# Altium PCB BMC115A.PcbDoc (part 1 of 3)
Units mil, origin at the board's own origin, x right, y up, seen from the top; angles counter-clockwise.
Board outline 5500 x 3200 mil, 4 copper layers (Top Layer, Signal Layer 1, Signal Layer 2, Bottom Layer), stack 61.6 mil thick; 199 components, 81 nets, 456 pads, 1349 vias.
Unrouted connection lines stored in the file: 741.
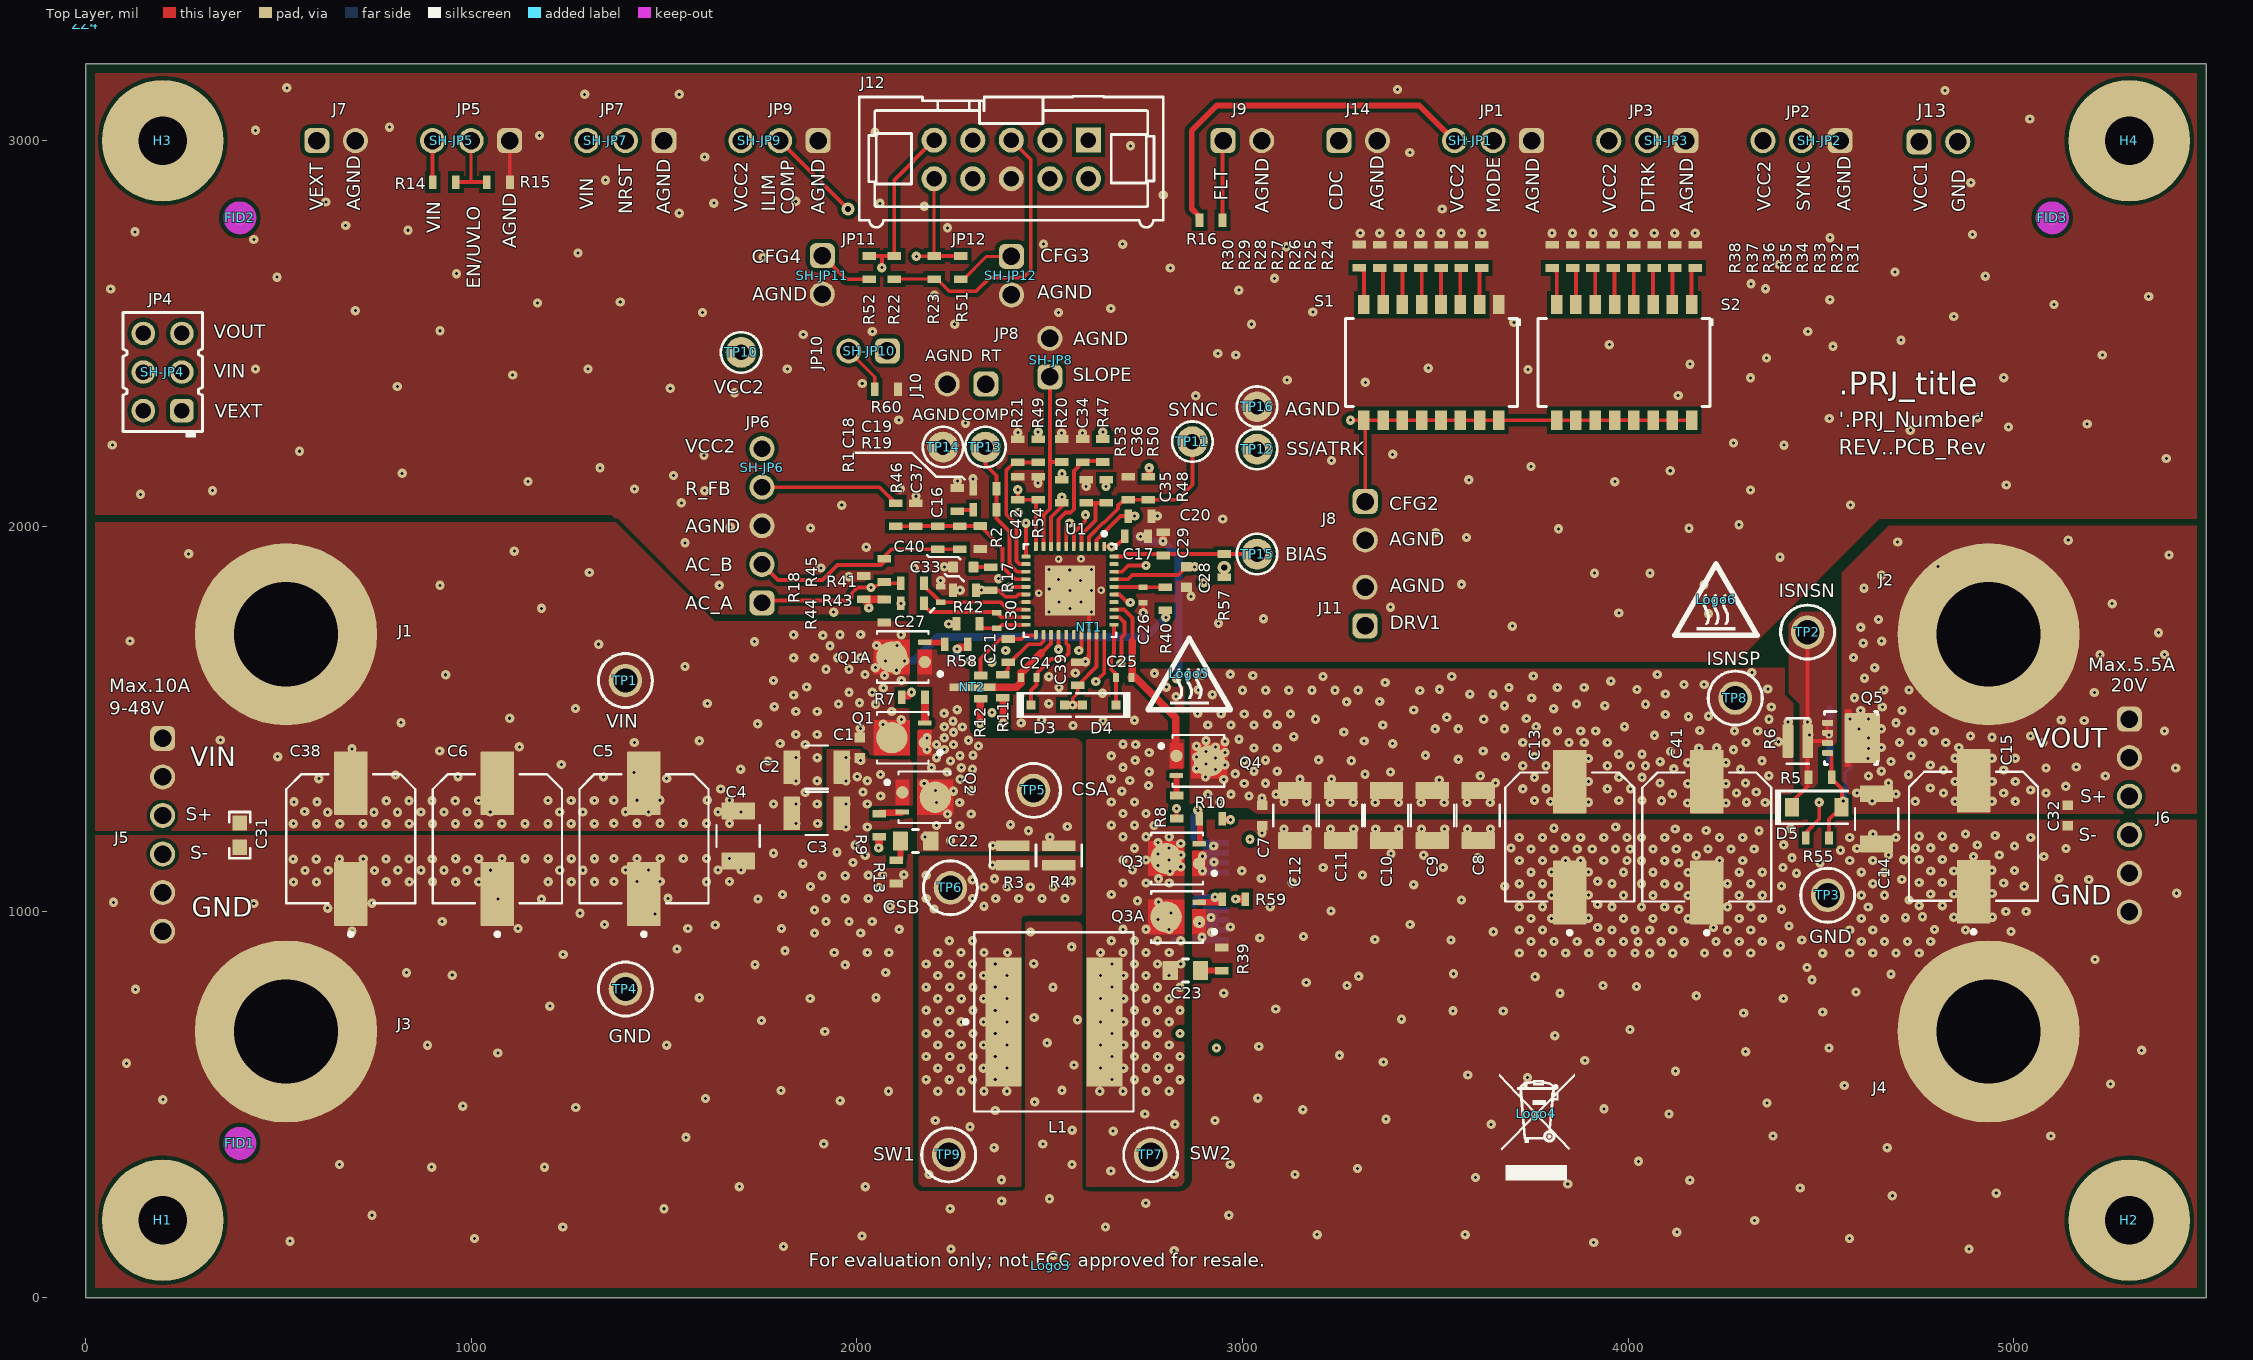
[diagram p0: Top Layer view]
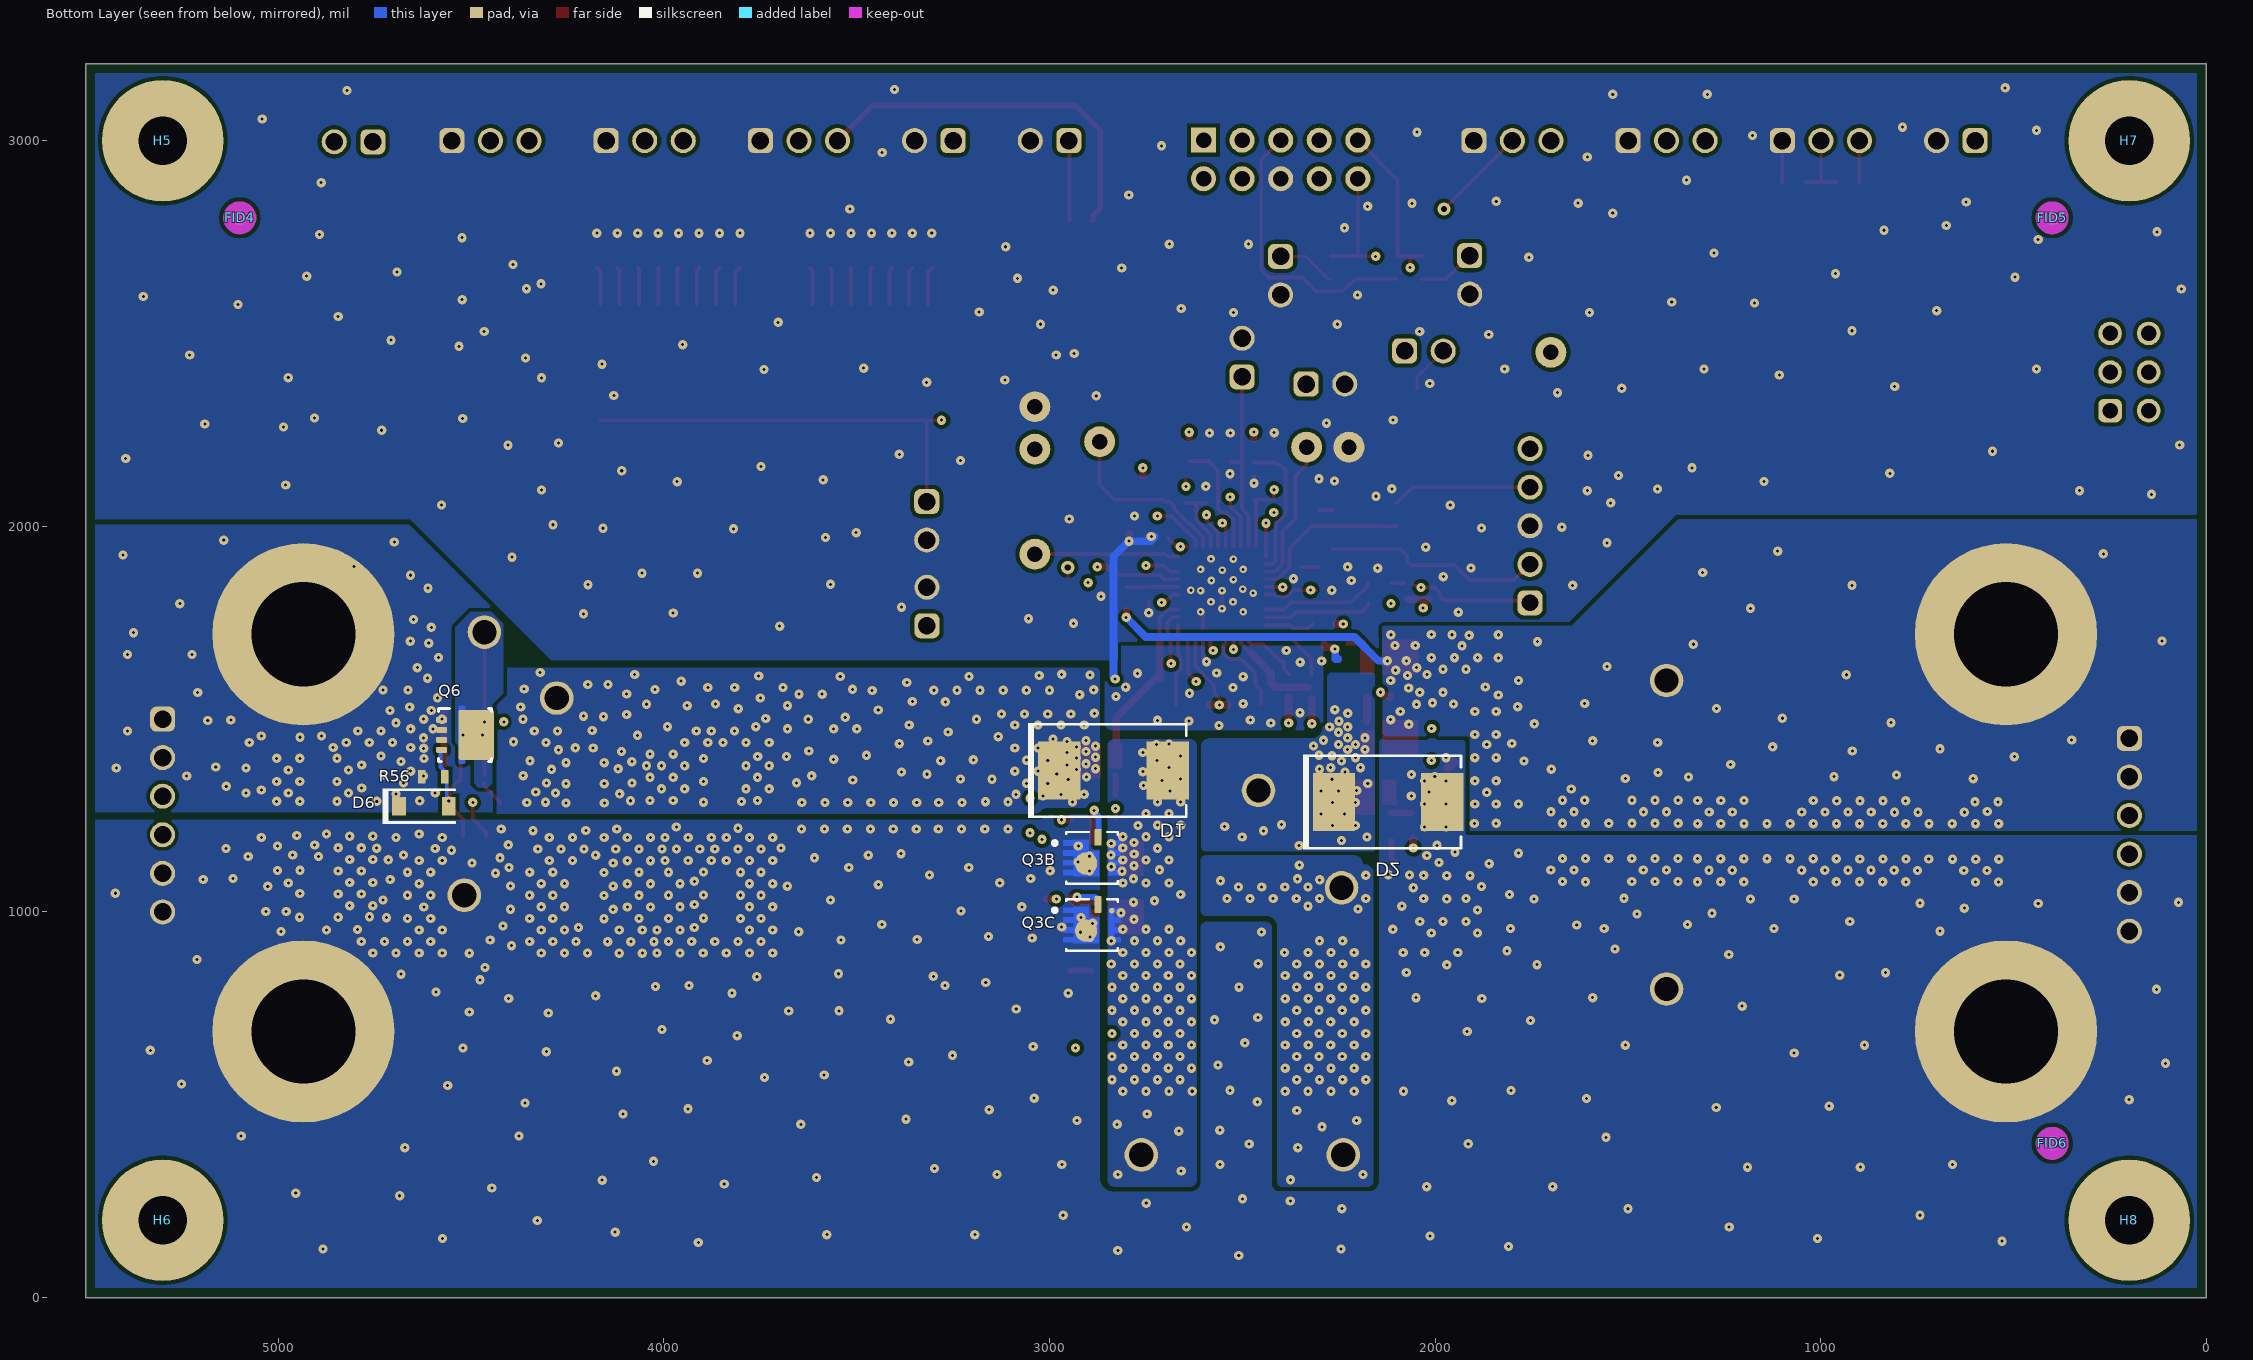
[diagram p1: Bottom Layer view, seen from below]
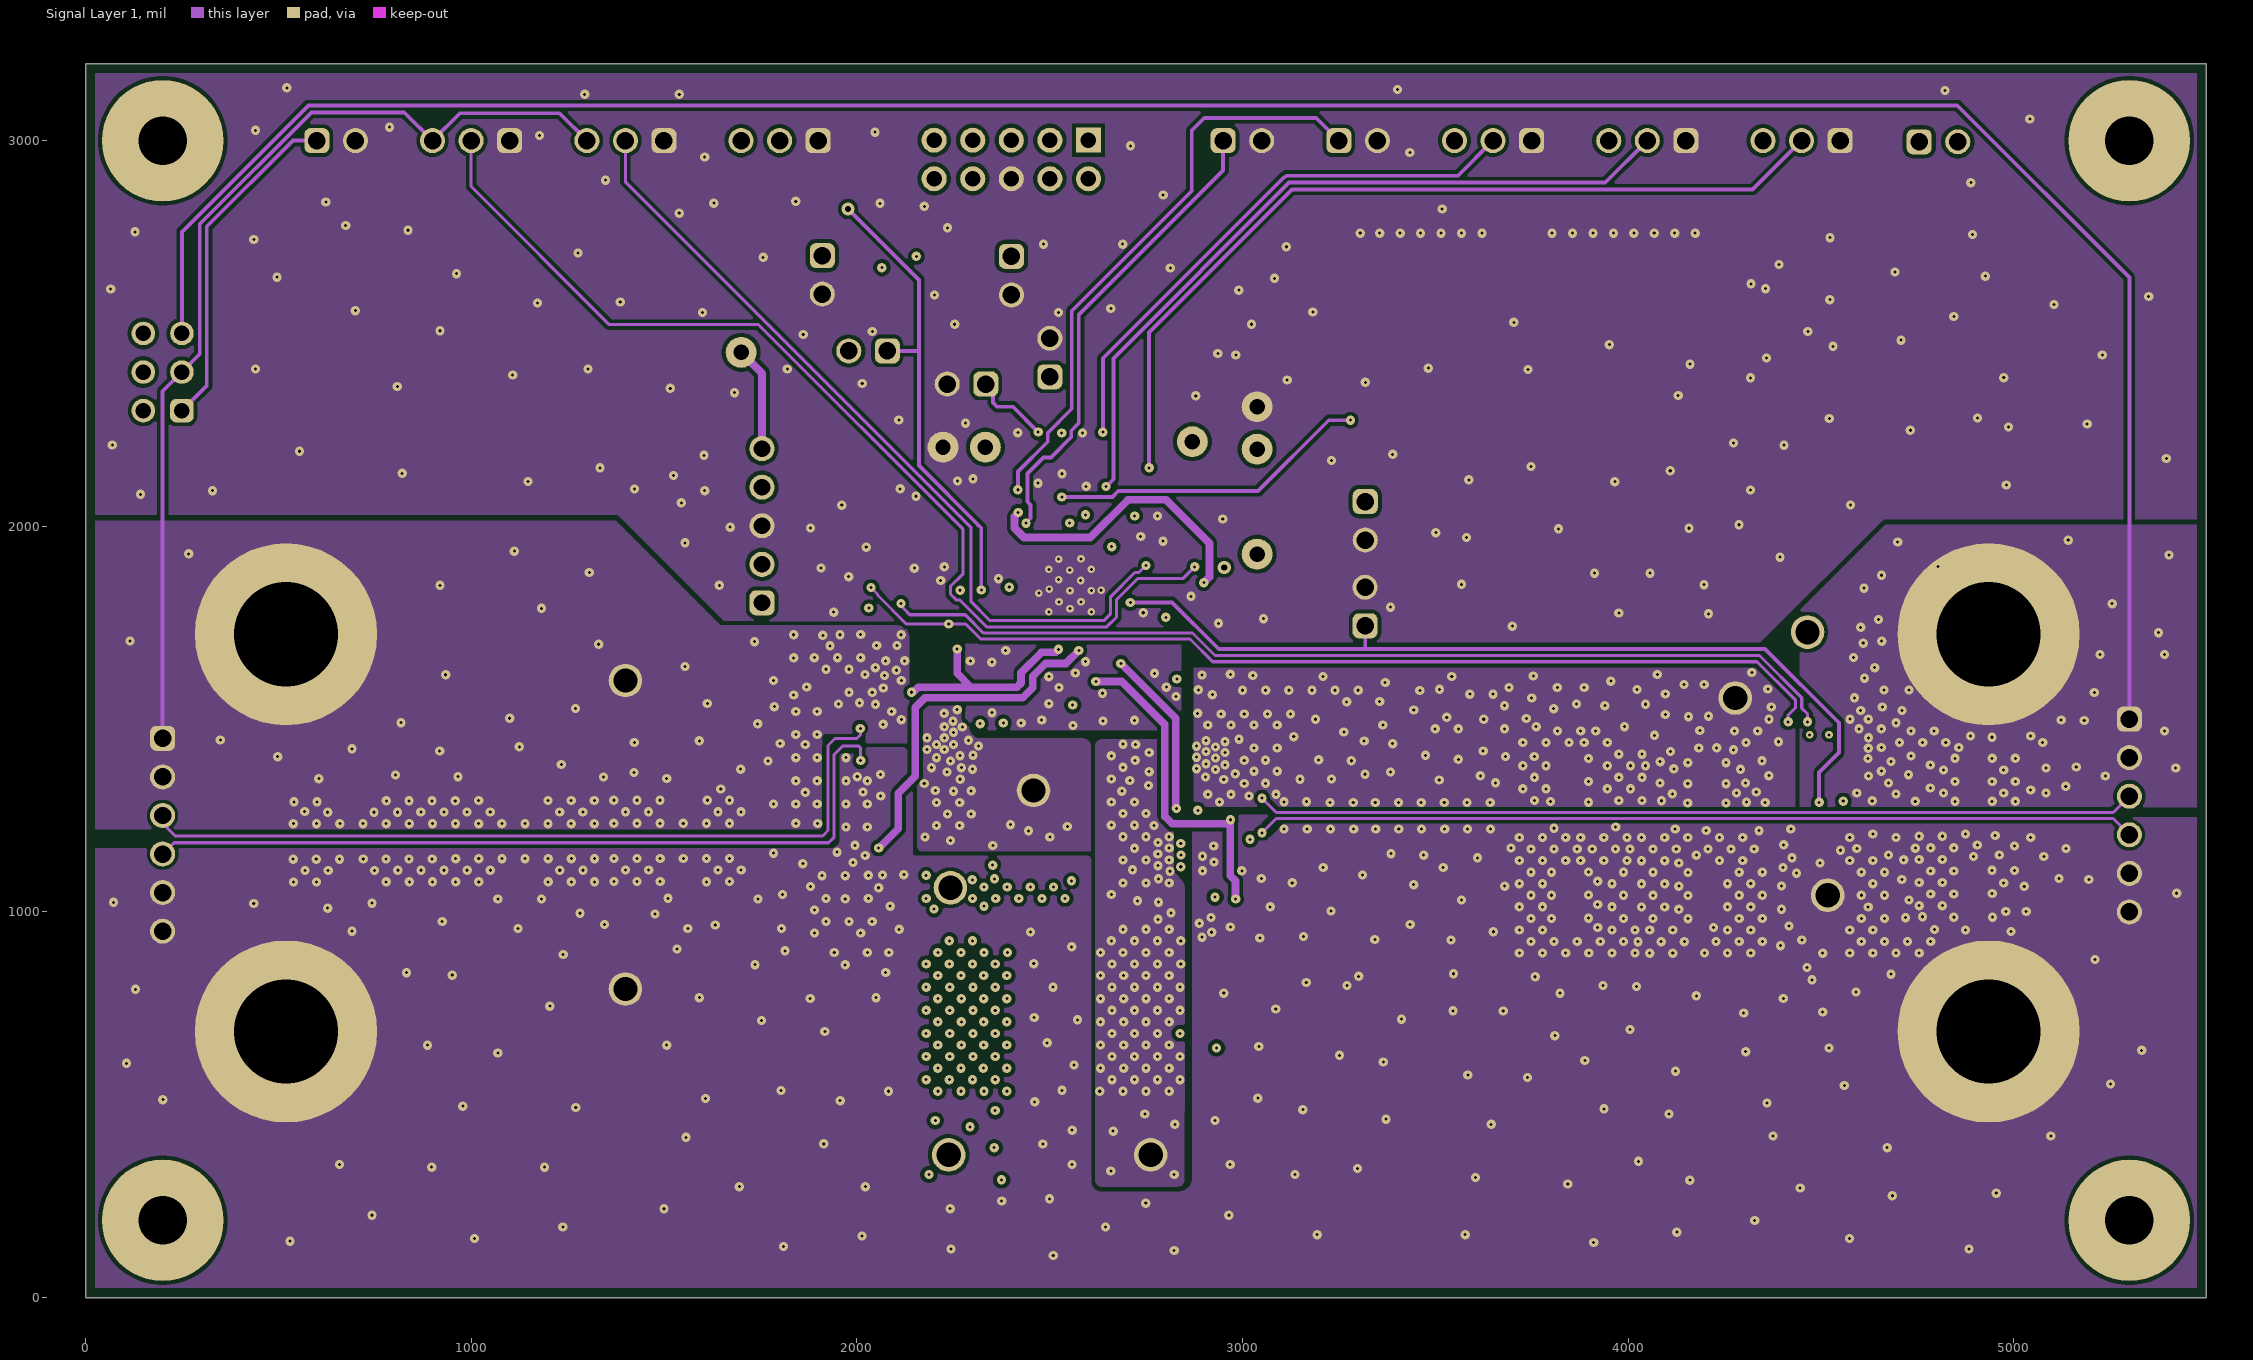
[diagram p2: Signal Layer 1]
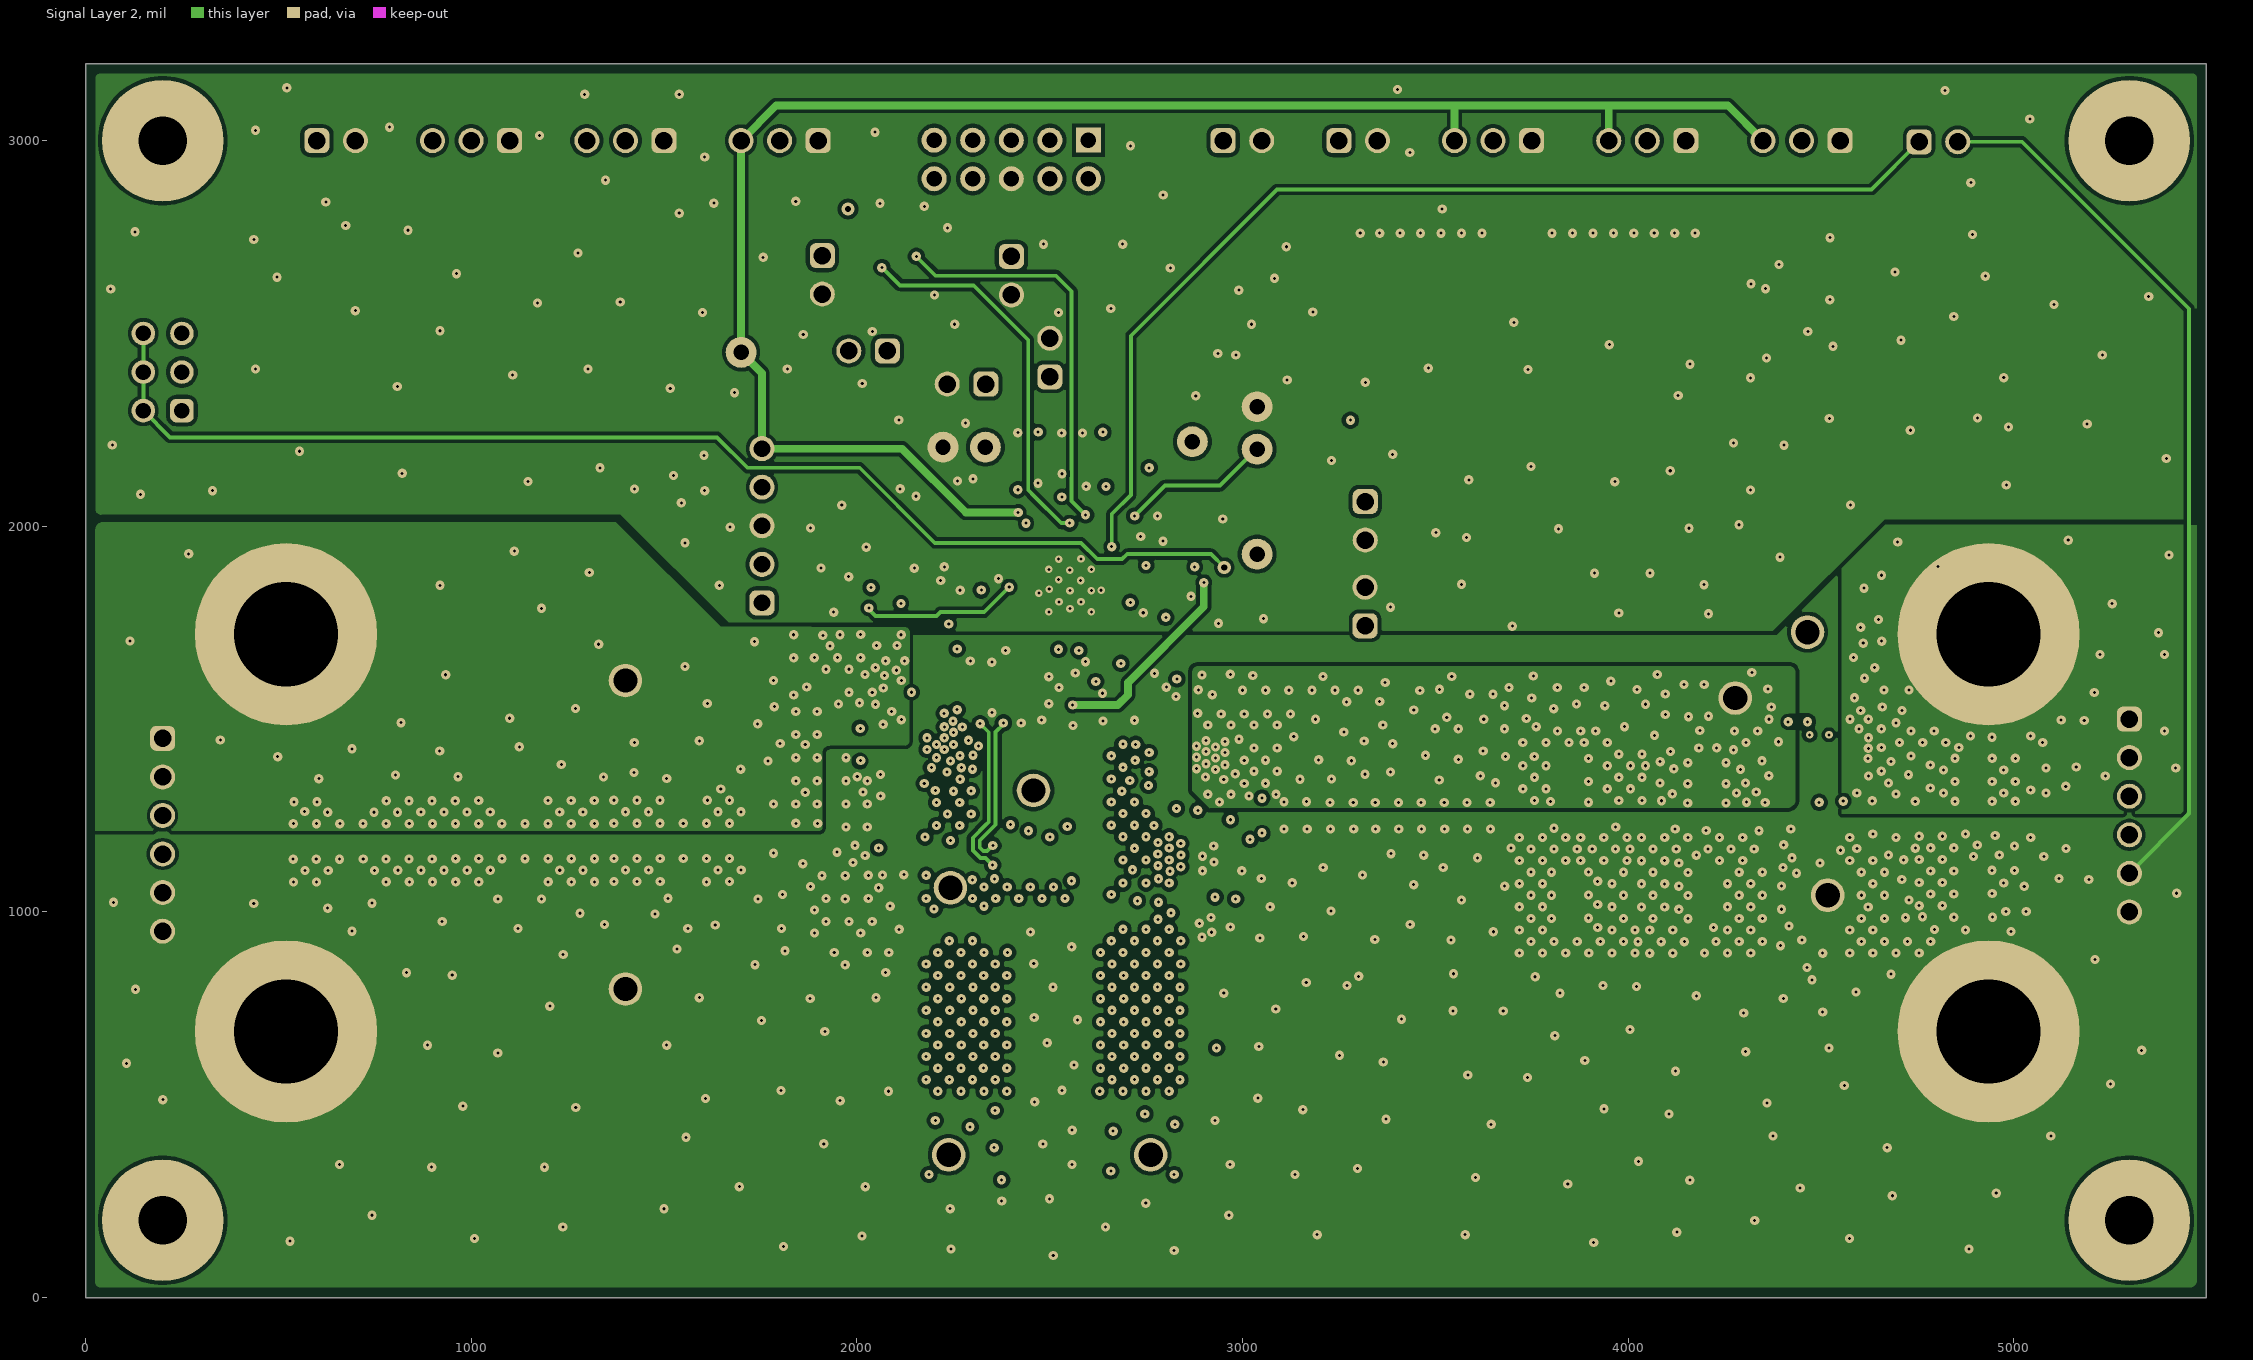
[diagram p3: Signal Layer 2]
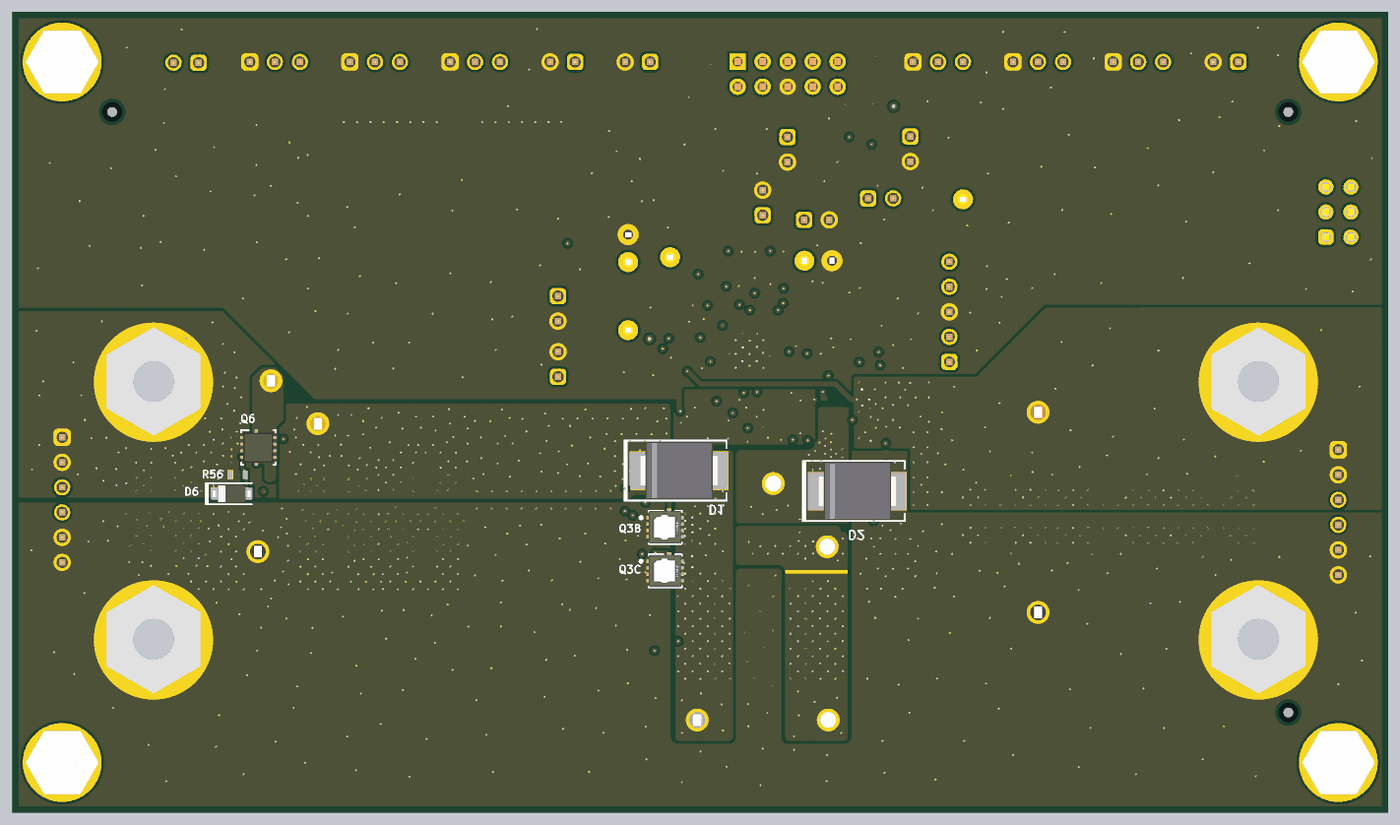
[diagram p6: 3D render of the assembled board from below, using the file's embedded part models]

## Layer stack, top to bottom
Top Solder: solder mask 0.4, Solder Resist, Dk 3.5
Top Layer: signal copper 2.8
Dielectric 1: prepreg 8, FR-4 High Tg, Dk 4.2
Signal Layer 1: signal copper 1.4
Dielectric 2: core 37.2, FR-4 High Tg, Dk 4.2
Signal Layer 2: signal copper 1.4
Dielectric 3: prepreg 8, FR-4 High Tg, Dk 4.2
Bottom Layer: signal copper 2.8
Bottom Solder: solder mask 0.4, Solder Resist, Dk 3.5

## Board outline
5500,0 5500,3200 0,3200 0,0

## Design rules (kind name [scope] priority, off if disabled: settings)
AcuteAngle [All] p1: minimum=4.50000000000000E+0001 checktracksonly=TRUE
AssemblyTestPointUsage [All] p1: valid=2
BoardOutlineClearance BoardOutlineClearance_MountingHoles [OnCopper and InComponentClass('Mounting Holes')] p1: gap=39.37 ignorepadtopadclearanceinfootprint=FALSE
BoardOutlineClearance BoardOutlineClearance_Poly [OnCopper and IsPoly] p2: gap=25 ignorepadtopadclearanceinfootprint=FALSE
BoardOutlineClearance [OnCopper and Not InComponentClass('Logo') and not InComponentClass('FiducialMark') and not InRegion(1000,500,4000,800) and not InPoly] p3: gap=40 ignorepadtopadclearanceinfootprint=FALSE
Clearance Clearance_Keepouts [((IsTrack Or IsArc) And Not InPoly) And IsFree and IsKeepOut vs ((IsTrack Or IsArc) And Not InPoly) And IsFree and IsKeepOut] p1: gap=0 ignorepadtopadclearanceinfootprint=FALSE
Clearance Clearance_Poly [InPolygon] p2: gap=10 ignorepadtopadclearanceinfootprint=TRUE
Clearance Clearance_FiducialMark [IsKeepOut and InComponentClass('FiducialMark') vs IsPad and InComponentClass('FiducialMark')] p3: gap=0 ignorepadtopadclearanceinfootprint=FALSE
Clearance [All] p4: gap=7.87 ignorepadtopadclearanceinfootprint=TRUE
ComponentClearance ComponentClearance_TP [InComponent('TP15')or InComponent('TP16')or InComponent('TP17')or InComponent('TP18')or InComponent('TP23')or InComponent('TP24')or InComponent('TP12')or InComponent('TP13')or InComponent('TP21')or InComponent('TP22')] p1: gap=10 collisioncheckmode=3 verticalgap=0 showdistances=FALSE
ComponentClearance ComponentClearance_NT1 [InComponent('NT1') or InComponent('NT2')] p2: gap=0 collisioncheckmode=3 verticalgap=0 showdistances=FALSE
ComponentClearance ComponentClearance_MountingHoles_FiducialMarks [InComponentClass('Mounting Holes') vs InComponentClass('FiducialMark')] p3: gap=50 collisioncheckmode=3 verticalgap=10 showdistances=FALSE
ComponentClearance ComponentClearance_Shunt [InComponentClass('Header') vs InComponent('SH-JP1') or InComponent('SH-JP2') or InComponent('SH-JP3') or InComponent('SH-JP4') or InComponent('SH-JP5') or InComponent('SH-JP6') or InComponent('SH-JP7') or InComponent('SH-JP8') or InComponent('SH-JP9') or InComponent('SH-JP10') or InComponent('SH-JP11') or InComponent('SH-JP12')] p4: gap=0 collisioncheckmode=3 verticalgap=0 showdistances=FALSE
ComponentClearance ComponentClearance_Logo [InComponentClass('Logo')] p5: gap=30 collisioncheckmode=3 verticalgap=10 showdistances=FALSE
ComponentClearance ComponentClearance_ScrewToNut [(HasFootprint('NY PMS 440 0025 PH')) vs (HasFootprint('Keystone_1902C'))] p6: gap=5 collisioncheckmode=3 verticalgap=10 showdistances=FALSE
ComponentClearance ComponentClearance_MountingHoles [InComponentClass('Mounting Holes')] p7: gap=100 collisioncheckmode=3 verticalgap=100000 showdistances=FALSE
ComponentClearance ComponentClearance_SmallPassives [HasFootprint('0201*') or HasFootprint('0402*') or HasFootprint('0508') or HasFootprint('0603*') or HasFootprint('0612') or HasFootprint('0805*') or HasFootprint('0815*') or HasFootprint('0830*') or HasFootprint('1206*') or HasFootprint('1210*') or HasFootprint('1808*') or HasFootprint('1812*') or HasFootprint('1825*') or HasFootprint('2010*') or HasFootprint('2220*') or HasFootprint('2225*') or HasFootprint('2512*') or HasFootprint('2728*') or HasFootprint('3518*') vs HasFootprint('0201*') or HasFootprint('0402*') or HasFootprint('0508') or HasFootprint('0603*') or HasFootprint('0612') or HasFootprint('0805*') or HasFootprint('0815*') or HasFootprint('0830*') or HasFootprint('1206*') or HasFootprint('1210*') or HasFootprint('1808*') or HasFootprint('1812*') or HasFootprint('1825*') or HasFootprint('2010*') or HasFootprint('2220*') or HasFootprint('2225*') or HasFootprint('2512*') or HasFootprint('2728*') or HasFootprint('3518*')] p8: gap=14.96 collisioncheckmode=3 verticalgap=10 showdistances=FALSE
ComponentClearance ComponentClearance_THtoSMT [IsThruComponent vs IsSMTComponent] p9: gap=30 collisioncheckmode=3 verticalgap=30 showdistances=FALSE
ComponentClearance ComponentClearance_THtoTH [IsThruComponent vs IsThruComponent] p10: gap=20 collisioncheckmode=3 verticalgap=30 showdistances=FALSE
ComponentClearance [All] p11: gap=20 collisioncheckmode=3 verticalgap=10 showdistances=FALSE
DiffPairsRouting [All] p1: maxlimit=100 minlimit=10 mostfreqgap=10 toplayer_minwidth=15 toplayer_maxwidth=15 toplayer_prefwidth=15 midlayer1_minwidth=15 midlayer1_maxwidth=15 midlayer1_prefwidth=15 midlayer2_minwidth=15 midlayer2_maxwidth=15 midlayer2_prefwidth=15 bottomlayer_minwidth=15 bottomlayer_maxwidth=15 bottomlayer_prefwidth=15 maxuncoupledlength=1000
FabricationTestPointUsage TestPointUsage [All] p1: valid=2 allowmultiple=FALSE
FabricationTestpoint Testpoint [All] p1: side=3 testpointundercomponent=TRUE minsize=40 maxsize=100 preferedsize=60 minholesize=0 maxholesize=40 preferedholesize=32 testpointgrid=1 allowsidetop=TRUE allowsidebottom=TRUE usegrid=TRUE gridtolerance=0.01
FanoutControl Fanout_LCC [IsLCC] p1: bgadir=Out bgaviamode=Centered fanoutstyle=Auto fanoutdirection=Alternating viagrid=1 // Fanout_LCC (Default Rule)
FanoutControl Fanout_BGA [IsBGA] p2: bgadir=Out bgaviamode=Centered fanoutstyle=Auto fanoutdirection=Alternating viagrid=1 // Fanout_BGA (Default Rule)
FanoutControl Fanout_Default [All] p4: bgadir=Out bgaviamode=Centered fanoutstyle=Auto fanoutdirection=Alternating viagrid=1 // Fanout_Default (Default Rule)
FanoutControl Fanout_Small [(CompPinCount < 5)] p5: bgadir=Out bgaviamode=Centered fanoutstyle=Auto fanoutdirection=OutThenIn viagrid=1 // Fanout_Small (Default Rule)
HoleSize [All] p1: absolutevalues=TRUE maxlimit=275 minlimit=7.87 maxpercent=80.000 minpercent=20.000
MinimumAnnularRing MinimumAnnularRing_QFN_Room [WithinRoom('QFN_Room')] p1: minimumring=5.9
MinimumAnnularRing MinimumAnnularRing_ThermalPadVias [IsVia and InAnyComponent] p2: minimumring=5.91
MinimumAnnularRing [All] p3: minimumring=7.87
MinimumSolderMaskSliver MinimumSolderMaskSliver_Logo [InComponentClass('Logo') vs InComponentClass('Logo')] p1: minsoldermaskwidth=0.7
MinimumSolderMaskSliver [All] p2: minsoldermaskwidth=3.94
PlaneConnect [All] p1: planeconnectstyle=Relief reliefexpansion=10 reliefentries=4 reliefconductorwidth=10 reliefairgap=10
PolygonConnect [All] p1: connectstyle=Direct reliefconductorwidth=10 reliefentries=4 polygonreliefangle="90 Angle" airgapwidth=10
RoomDefinition QFN_Room [False] p1: confinementstyle=ConfineIn formatcopy=TRUE lockcomponents=FALSE outline 2447.29,1945.95 2657.01,1945.95 2657.01,1733.12 2447.29,1733.12
RoutingVias RoutingVias_QFN_Room [WithinRoom('QFN_Room')] p1: holewidth=28 width=50 viastyle="Through Hole" minholewidth=7.87 minwidth=19.68 maxholewidth=28 maxwidth=50
RoutingVias ThermalPadVias [IsVia and InAnyComponent] p2: holewidth=7.87 width=19.68 viastyle="Through Hole" minholewidth=7.87 minwidth=19.68 maxholewidth=12.99 maxwidth=23.62
RoutingVias [All] p3: holewidth=16 width=34 viastyle="Through Hole" minholewidth=7.87 minwidth=24 maxholewidth=40 maxwidth=65
SilkToBoardRegionClearance [Not ((IsComment or IsDesignator) And (Hide <> 'False')) and not InRegion(1000,500,4000,800)] p1:
SilkToSilkClearance SilkToSilkClearance_Pb-FreeLogo [(HasFootprint('Pb-Free_Overlay_Medium') OR HasFootprint('Pb-Free_Overlay_Small')) vs (HasFootprint('Pb-Free_Overlay_Medium') OR HasFootprint('Pb-Free_Overlay_Small'))] p1: silktosilkclearance=0
SilkToSilkClearance [All] p2: silktosilkclearance=3.94
SilkToSolderMaskClearance SilkToComponentPadClearance [(IsPad or IsFill or IsRegion) and InAnycomponent] p1: minsilkscreentomaskgap=5 clearancetoexposedcopper=TRUE
SilkToSolderMaskClearance "Silk to Solder Mask Opening" [All] p2: minsilkscreentomaskgap=3.94 clearancetoexposedcopper=FALSE
SolderMaskExpansion [All] p1: expansion=1.97 istentingtop=FALSE
UnRoutedNet [All] p1: checkbadconnections=TRUE
Width [All] p1: maxlimit=100 minlimit=6 preferedwidth=10
14 further rules are at their usual default settings.

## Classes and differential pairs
component class Header: J5 J6 J7 J8 J9 J10 J11 J13 J14 JP1 JP2 JP3 JP4 JP5 JP6 JP7 JP8 JP9 JP10 JP11 JP12
component class BMC115A: 6 C1 C2 C3 C4 C5 C6 C7 C8 C9 C10 C11 C12 C13 C14 C15 C16 C17 C18 C19 C20 C21 C22 C23 C24 C25 C26 C27 C28 C29 C30 C31 C32 C33 C34 C35 C36 C37 C38 C39 C40 C41 C42 D1 D2 D3 D4 D5 D6 J1 J2 J3 J4 J5 J6 J7 J8 J9 J10 J11 J12 J13 J14 JP1 JP2 JP3 JP4 JP5 JP6 JP7 JP8 JP9 JP10 JP11 JP12 L1 NT1 NT2 Q1 Q1A Q2 Q3 Q3A Q3B Q3C Q4 Q5 Q6 R1 R2 R3 R4 R5 R6 R7 R8 R9 R10 R11 R12 R13 R14 R15 R16 R17 R18 R19 R20 R21 R22 R23 R24 R25 R26 R27 R28 R29 R30 R31 R32 R33 R34 R35 R36 R37 R38 R39 R40 R41 R42 R43 R44 R45 R46 R47 R48 R49 R50 R51 R52 R53 R54 R55 R56 R57 R58 R59 R60 S1 S2 TP1 TP2 TP3 TP4 TP5 TP6 TP7 TP8 TP9 TP10 TP11 TP12 TP13 TP14 TP15 TP16 U1
component class "Mounting Holes": H1 H2 H3 H4
component class BMC115A_Hardware: FID1 FID2 FID3 FID4 FID5 FID6 H1 H2 H3 H4 H5 H6 H7 H8 Logo3 Logo4 Logo5 Logo6 SH-JP1 SH-JP2 SH-JP3 SH-JP4 SH-JP5 SH-JP6 SH-JP7 SH-JP8 SH-JP9 SH-JP10 SH-JP11 SH-JP12 ZZ2 ZZ3 ZZ4
component class FiducialMark: FID1 FID2 FID3 FID4 FID5 FID6
component class AssemblyNote: ZZ2 ZZ3 ZZ4

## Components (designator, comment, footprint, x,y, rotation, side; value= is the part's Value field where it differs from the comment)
C1 "GCM188L81H104KA57D" FP-GCM188L81H104KA57D_0603-MFG 2008.08,1425.95 r270 top
C2 "C3225X7R2A106K250AC" FP-C3225X7R2A106K250AC_1210-MFG 1896,1375.42 r180 top value=10µF
C3 "C3225X7R2A106K250AC" FP-C3225X7R2A106K250AC_1210-MFG 1896,1255.42 r180 top value=10µF
C4 "C3225X7R2A106K250AC" FP-C3225X7R2A106K250AC_1210-MFG 1692.3,1196.85 r90 top value=10µF
C5 "A768KE276M1JLAE054" FP-A768KE276M1JLAE054_SMT_CAP_8MM3_8MM3-0 1448,1190 r90 top value=27µF
C6 "A768KE276M1JLAE054" FP-A768KE276M1JLAE054_SMT_CAP_8MM3_8MM3-0 1068,1190 r90 top value=27µF
C7 "GCM188L81H104KA57D" FP-GCM188L81H104KA57D_0603-MFG 3051,1250 r270 top
C8 "C3225X7R2A106K250AC" FP-C3225X7R2A106K250AC_1210-MFG 3611.57,1250 r90 top value=10µF
C9 "C3225X7R2A106K250AC" FP-C3225X7R2A106K250AC_1210-MFG 3492.57,1250 r90 top value=10µF
C10 "C3225X7R2A106K250AC" FP-C3225X7R2A106K250AC_1210-MFG 3373.57,1250 r90 top value=10µF
C11 "C3225X7R2A106K250AC" FP-C3225X7R2A106K250AC_1210-MFG 3255,1250 r90 top value=10µF
C12 "C3225X7R2A106K250AC" FP-C3225X7R2A106K250AC_1210-MFG 3136,1250 r90 top value=10µF
C13 "A768KE276M1JLAE054" FP-A768KE276M1JLAE054_SMT_CAP_8MM3_8MM3-0 3848.71,1194.11 r90 top value=27µF
C14 "C3225X7R2A106K250AC" FP-C3225X7R2A106K250AC_1210-MFG 4644.4,1241.07 r90 top value=10µF
C15 "A768KE276M1JLAE054" FP-A768KE276M1JLAE054_SMT_CAP_8MM3_8MM3-0 4896.03,1196.11 r90 top value=27µF
C16 "GRM1885C2A200JA01D" 0603S 2209.91,1970.42 r90 top value=20pF
C17 "GRT188R61A226ME13D" 0603S 2725.01,1974.28 r180 top value=22µF
C18 "C0603C123K5RACTU" 0603S 2261.07,2069.11 r90 top value=0.012uF
C19 "06035A221FAT2A" 0603S 2332.19,2097.1 r180 top value=220pF
C20 "CC0603KRX7R9BB203" 0603S 2734.01,2026.62 r0 top value=0.02uF
C21 "GCM1885C1H101JA16J" 0603S 2392.68,1677.64 r270 top value=100pF
C22 "GRM2195C2A681JA01D" 0805_HV1 2152.64,1183.61 r0 top value=680pF
C23 "GRM2195C2A681JA01D" 0805_HV1 2852.29,848.15 r180 top value=680pF
C24 "GCM155R71H104KE02D" 0402S 2445.98,1608 r0 top value=0.1uF
C25 "GCM155R71H104KE02D" 0402S 2692.04,1608 r180 top value=0.1uF
C26 "GRM155R62A104KE14D" 0402S 2742.37,1821.95 r90 top value=0.1uF
C27 "GRM155R62A104KE14D" 0402S 2217.79,1823.16 r90 top value=0.1uF
C28 "GCM188L81H104KA57D" FP-GCM188L81H104KA57D_0603-MFG 2854.99,1868.35 r270 top
C29 "CGA3E3X7S2A104K080AB" 0603S 2794.32,1954.37 r270 top value=0.1uF
C30 "0402BB104KW500" 0402S 2362.79,1755.65 r270 top value=0.1uF
C31 "GCJ188R72A104KA01D" 0603 400,1199.19 r270 top value=0.1uF
C32 "GCM188L81H104KA57D" FP-GCM188L81H104KA57D_0603-MFG 5140,1250 r270 top
C33 "06035A101FAT2A" 0603S 2279.35,1834.12 r180 top value=100pF
C34 "06031C102JAT2A" 0603S 2585.69,2196.38 r90 top value=1000pF
C35 "06031C102JAT2A" 0603S 2703.56,2098.72 r90 top value=1000pF
C36 "06031C102JAT2A" 0603S 2594.9,2090.8 r90 top value=1000pF
C37 "GRM1885C1H151JA01D" 0603S 2153.05,2029.98 r90 top value=150pF
C38 "A768KE276M1JLAE054" FP-A768KE276M1JLAE054_SMT_CAP_8MM3_8MM3-0 688,1190 r90 top value=27µF
C39 "GRT188R61A226ME13D" 0603S 2573,1617.49 r270 top value=22µF
C40 "GCM188L81H104KA57D" FP-GCM188L81H104KA57D_0603-MFG 2275.8,1894.43 r180 top
C41 "A768KE276M1JLAE054" FP-A768KE276M1JLAE054_SMT_CAP_8MM3_8MM3-0 4204.38,1194.11 r90 top value=27µF
C42 "06035A560FAT2A" 0603S 2417.93,2098.72 r90 top value=56pF
D1 "B560C-13-F" SMC 2834.46,1366.89 r180 bottom value=60V
D2 "B560C-13-F" SMC 2121.96,1284.89 r180 bottom value=60V
D3 "PMEG6010CEJ,115" SOD-323F 2495,1536.5 r0 top value=60V
D4 "PMEG6010CEJ,115" SOD-323F 2629,1536.5 r180 top value=60V
D5 "MMSZ4697T1G" SOD-123 4489.48,1271 r0 top value=10V
D6 "MMSZ4697T1G" SOD-123 4622.46,1274.26 r180 bottom value=10V
FID1 "Fiducial" Fiducial10-20 400,400 r0 top
FID2 "Fiducial" Fiducial10-20 400,2800 r0 top
FID3 "Fiducial" Fiducial10-20 5100,2800 r0 top
FID4 "Fiducial" Fiducial10-20 5100,2800 r180 bottom
FID5 "Fiducial" Fiducial10-20 400,2800 r180 bottom
FID6 "Fiducial" Fiducial10-20 400,400 r180 bottom
H1 "NY PMS 440 0025 PH" "NY PMS 440 0025 PH" 200,200 r0 top
H2 "NY PMS 440 0025 PH" "NY PMS 440 0025 PH" 5300,200 r0 top
H3 "NY PMS 440 0025 PH" "NY PMS 440 0025 PH" 200,3000 r0 top locked
H4 "NY PMS 440 0025 PH" "NY PMS 440 0025 PH" 5300,3000 r0 top
H5 "1902C" Keystone_1902C 5300,3000 r180 bottom locked
H6 "1902C" Keystone_1902C 5300,200 r180 bottom
H7 "1902C" Keystone_1902C 200,3000 r180 bottom locked
H8 "1902C" Keystone_1902C 200,200 r180 bottom locked
J1 "108-0740-001" Johnson_108-0740-001 520,1720 r0 top
J2 "108-0740-001" Johnson_108-0740-001 4935,1720 r0 top
J3 "108-0740-001" Johnson_108-0740-001 520,690 r0 top
J4 "108-0740-001" Johnson_108-0740-001 4935,690 r0 top
J5 "61300611121" WURTH_61300611121 200,1200 r270 top
J6 "61300611121" WURTH_61300611121 5300,1250 r270 top
J7 "61300211121" WURTH_61300211121 650,3000 r0 top
J8 "61300211121" WURTH_61300211121 3318.61,2014.15 r270 top
J9 "61300211121" WURTH_61300211121 3000,3000 r0 top
J10 "61300211121" WURTH_61300211121 2284.52,2368.9 r180 top
J11 "61300211121" WURTH_61300211121 3318,1791.92 r90 top
J12 "N2510-6002-RB" CONN_2510-6002 2400.67,2951.23 r180 top
J13 "61300211121" WURTH_61300211121 4805,2997 r0 top
J14 "61300211121" WURTH_61300211121 3300,3000 r0 top
JP1 "61300311121" WURTH_61300311121 3650,3000 r180 top
JP2 "61300311121" WURTH_61300311121 4450,3000 r180 top
JP3 "61300311121" WURTH_61300311121 4050,3000 r180 top
JP4 "HTSW-103-07-G-D" Samtec_HTSW-103-07-x-D 200,2400 r180 top
JP5 "61300311121" WURTH_61300311121 1000,3000 r180 top
JP6 "61300511121" Wurth_61300511121 1754.31,2001.32 r90 top
JP7 "61300311121" WURTH_61300311121 1400,3000 r180 top
JP8 "61300211121" WURTH_61300211121 2500.64,2437.56 r90 top
JP9 "61300311121" WURTH_61300311121 1800,3000 r180 top
JP10 "61300211121" WURTH_61300211121 2029.27,2454.69 r180 top
JP11 "61300211121" WURTH_61300211121 1910.65,2652 r270 top
JP12 "61300211121" WURTH_61300211121 2401.09,2649.94 r270 top
L1 "XGL1060-332MEC" FP-XGL1060-332MEC_SMT2_10MM0_11MM3-MFG 2511.06,714.89 r0 top value=3.3uH
Logo3 "FCC disclaimer" FCC_disclaimer 2503,82 r0 top
Logo4 "WEEE logo" WEEE_Minimum 3761.84,476.02 r0 top
Logo5 "CAUTION HOT SURFACE" IEC_HotSurface_Small 2862.25,1617.33 r0 top
Logo6 "CAUTION HOT SURFACE" IEC_HotSurface_Small 4228.2,1810 r0 top
NT1 "Net-Tie" Net-Tie_10mil 2602.22,1738.34 r90 top net-tie
NT2 "Net-Tie" Net-Tie_20milWide_60milLong 2299.97,1582.63 r180 top net-tie
Q1 "ISZ034N06LM5ATMA1" FP-ISZ034N06LM5ATMA1_TSDSON8-MFG 2119.33,1451.68 r90 top
Q1A "ISZ034N06LM5ATMA1" FP-ISZ034N06LM5ATMA1_TSDSON8-MFG 2119.33,1660.93 r90 top
Q2 "ISZ034N06LM5ATMA1" FP-ISZ034N06LM5ATMA1_TSDSON8-MFG 2175.23,1297.31 r270 top
Q3 "ISZ034N06LM5ATMA1" FP-ISZ034N06LM5ATMA1_TSDSON8-MFG 2830.6,1138.28 r90 top
Q3A "ISZ034N06LM5ATMA1" FP-ISZ034N06LM5ATMA1_TSDSON8-MFG 2830.61,986.79 r90 top
Q3B "IQE022N06LM5CGSCATMA1" FP-IQE022N06LM5CGSCATMA1_PG-WHTFN-9-MFG 2889.88,1140.21 r270 bottom
Q3C "IQE022N06LM5CGSCATMA1" FP-IQE022N06LM5CGSCATMA1_PG-WHTFN-9-MFG 2889.88,965.98 r270 bottom
Q4 "ISZ034N06LM5ATMA1" FP-ISZ034N06LM5ATMA1_TSDSON8-MFG 2885.91,1391.84 r270 top
Q5 "SI7415DN-T1-GE3" PowerPAK_1212-8#1 4578.01,1451.29 r0 top value=-60V
Q6 "SI7415DN-T1-GE3" PowerPAK_1212-8#2 4516.2,1459.16 r180 bottom value=-60V
R1 "RC0603FR-0782KL" 0603S 2266.51,1970.42 r270 top value=82.0k
R2 "RC0603FR-074K3L" 0603S 2320.21,1970.86 r90 top value=4.30k
R3 "KRL2012E-M-R005-F-T5" FP-KRL2012E-M-R005-F-T5_0805_WIDE-MFG 2404.24,1146.44 r90 top value=5m
R4 "KRL2012E-M-R005-F-T5" FP-KRL2012E-M-R005-F-T5_0805_WIDE-MFG 2524.24,1146.44 r90 top value=5m
R5 "CRCW0603180KJNEA" 0603S 4498.01,1349.04 r180 top value=180k
R6 "KRL2012E-C-R010-F-T05" FP-KRL2012E-C-R010-F-T05_0508-MFG 4440.29,1443 r0 top value=10m
R7 "CRCW06033R00JNEA" 0603S 2146.89,1556 r0 top value=3.0
R8 "CRCW06033R00JNEA" 0603S 2829.13,1272 r90 top value=3.0
R9 "CRCW06033R00JNEA" 0603S 2058.6,1224.84 r270 top value=3.0
R10 "CRCW06033R00JNEA" 0603S 2918,1241.94 r0 top value=3.0
R11 "CRCW060310R0FKEAHP" 0603S 2378,1585 r270 top value=10.0
R12 "CRCW060310R0FKEAHP" 0603S 2321,1583 r270 top value=10.0
R13 "CRCW06033R00JNEA" 0603S 2102.27,1103.58 r90 top value=3.0
R14 "RC0603FR-0775KL" 0603S 930.36,2892.68 r180 top value=75.0k
R15 "RC0603FR-0712K7L" 0603S 1070.61,2892.68 r180 top value=12.7k
R16 "RT0603BRD0710KL" 0603S 2918.51,2793.22 r180 top value=10.0k
R17 "RMCF0603ZT0R00" 0603S 2347.75,1864.12 r270 top value=0
R18 "RC0603FR-074K3L" 0603S 2017.44,1841.01 r270 top value=4.30k
R19 "CRCW06037K15FKEA" 0603S 2332.19,2042.59 r0 top value=7.15k
R20 "RC0603FR-075K1L" 0603S 2531.4,2196.52 r270 top value=5.10k
R21 "RC0603FR-0751KL" 0603S 2417.36,2195.75 r270 top value=51.0k
R22 "RC0603FR-072KL" 0603S 2097.58,2670.79 r270 top value=2.00k
R23 "RC0603FR-072KL" 0603S 2200.92,2670.85 r270 top value=2.00k
R24 "CRCW0603511RFKEA" 0603S 3621,2700 r270 top value=511
R25 "CRCW06031K15FKEA" 0603S 3568,2700 r270 top value=1.15k
R26 "RC0603FR-071K87L" 0603S 3515,2700 r270 top value=1.87k
R27 "RC0603FR-072K7L" 0603S 3462,2700 r270 top value=2.70k
R28 "CRCW06033K83FKEA" 0603S 3409,2700 r270 top value=3.83k
R29 "RC0603FR-075K1L" 0603S 3356,2700 r270 top value=5.10k
R30 "RC0603FR-076K49L" 0603S 3303.61,2700.47 r270 top value=6.49k
R31 "RC0603FR-078K25L" 0603S 4174,2700 r270 top value=8.25k
R32 "CRCW060310K5FKEA" 0603S 4121,2700 r270 top value=10.5k
R33 "RC0603FR-0713K3L" 0603S 4068,2700 r270 top value=13.3k
R34 "CRCW060316K2FKEA" 0603S 4015,2700 r270 top value=16.2k
R35 "RC0603FR-0720K5L" 0603S 3962,2700 r270 top value=20.5k
R36 "CRCW060324K9FKEA" 0603S 3909,2700 r270 top value=24.9k
R37 "CRCW060330K1FKEA" 0603S 3856,2700 r270 top value=30.1k
R38 "CRCW060335K7FKEA" 0603S 3803,2700 r270 top value=35.7k
R39 "CRCW06033R00JNEA" 0603S 2946.94,877.68 r270 top value=3.0
R40 "RMCF0603ZT0R00" 0603S 2800.28,1811.92 r270 top value=0
R41 "RMCF0603ZT0R00" 0603S 2144.38,1852.68 r180 top value=0
R42 "RMCF0603ZT0R00" 0603S 2288.38,1747 r180 top value=0
R43 "RMCF0603ZT0R00" 0603S 2144.38,1800 r180 top value=0
R44 "RC0603FR-0782KL" 0603S 2071.17,1780.32 r270 top value=82.0k
R45 "RC0603FR-0710RL" 0603S 2070.79,1885.58 r270 top value=10.0
R46 "RMCF0603ZT0R00" 0603S 2100.43,2029.98 r90 top value=0
R47 "RMCF0603ZT0R00" 0603S 2638.15,2196.57 r270 top value=0
R48 "RMCF0603ZT0R00" 0603S 2756.28,2098.72 r270 top value=0
R49 "RMCF0603ZT0R00" 0603S 2470.26,2195.75 r90 top value=0
R50 "RMCF0603ZT0R00" 0603S 2647.23,2090.8 r270 top value=0
R51 "RC0603FR-076K49L" 0603S 2269.93,2670.85 r90 top value=6.49k
R52 "RC0603FR-078K25L" 0603S 2032.57,2670.73 r90 top value=8.25k
R53 "CRCW06032K70JNEA" 0603S 2531.4,2090.8 r270 top value=2.7k
R54 "CRCW060340K2FKEA" 0603S 2470.26,2098.72 r270 top value=40.2k
R55 "CRCW060343K0JNEA" 0603S 4491.1,1191.65 r0 top value=43k
R56 "CRCW0603180KJNEA" 0603S 4598.3,1350 r0 bottom value=180k
R57 "RMCF0603ZT0R00" 0603S 2952.3,1898.06 r270 top value=0
R58 "CRCW06033R00JNEA" 0603S 2258.08,1694.14 r180 top value=3.0
R59 "CRCW06033R00JNEA" 0603S 2977.58,1033.22 r0 top value=3.0
R60 "RC0603FR-0718KL" 0603S 2076.66,2355.82 r180 top value=18.0k
S1 "218-8LPST" SW_218-8LP 3490,2425 r270 top
S2 "218-8LPST" SW_218-8LP 3990,2425 r270 top
SH-JP1 "M7582-05" Harwin_M7582-05 3592.48,3000 r0 top
SH-JP2 "M7582-05" Harwin_M7582-05 4497.59,3000 r0 top
SH-JP3 "M7582-05" Harwin_M7582-05 4101,3000 r0 top
SH-JP4 "M7582-05" Harwin_M7582-05 200,2400 r180 top
SH-JP5 "M7582-05" Harwin_M7582-05 949.87,3000 r180 top
SH-JP6 "M7582-05" Harwin_M7582-05 1754.31,2151.71 r90 top
SH-JP7 "M7582-05" Harwin_M7582-05 1348.99,3000 r180 top
SH-JP8 "M7582-05" Harwin_M7582-05 2504.23,2430.27 r90 top
SH-JP9 "M7582-05" Harwin_M7582-05 1748.72,3000 r180 top
SH-JP10 "M7582-05" Harwin_M7582-05 2032.75,2454.32 r0 top
SH-JP11 "M7582-05" Harwin_M7582-05 1910.32,2650.3 r90 top
SH-JP12 "M7582-05" Harwin_M7582-05 2399.76,2650.3 r90 top
TP1 "5010" Keystone5010 1400,1600 r180 top
TP2 "5013" Keystone5013 4465.49,1725.49 r180 top
TP3 "5011" Keystone5011 4517.79,1043.16 r180 top
TP4 "5011" Keystone5011 1400,800 r180 top
TP5 "5012" Keystone5012 2458.3,1315.08 r0 top
TP6 "5012" Keystone5012 2242.77,1062.59 r0 top
TP7 "5128" Keystone5128 2762.06,370 r0 top
TP8 "5013" Keystone5013 4278.02,1554.43 r0 top
TP9 "5012" Keystone5012 2238.4,370 r0 top
TP10 "5004" Keystone5004 1700,2450.86 r90 top
TP11 "5004" Keystone5004 2870.29,2219.44 r270 top
TP12 "5004" Keystone5004 3038,2200 r270 top
TP13 "5004" Keystone5004 2333.66,2205.39 r0 top
TP14 "5001" Keystone5001 2223.66,2205.39 r0 top
TP15 "5004" Keystone5004 3038,1927.91 r90 top
TP16 "5001" Keystone5001 3038,2310 r90 top
U1 "LM51772RHAR" RHA0040P-MFG 2553,1833 r270 top
ZZ2 "These assemblies are ESD sensitive, ESD precautions shall be observed." AssemblyNote 0,3500 r0 top
ZZ3 "These assemblies must be clean and free from flux and all contaminants. Use of no clean flux is not acceptable." AssemblyNote 0,3400 r0 top
ZZ4 "These assemblies must comply with workmanship standards IPC-A-610 Class 2, unless otherwise specified." AssemblyNote 0,3300 r0 top

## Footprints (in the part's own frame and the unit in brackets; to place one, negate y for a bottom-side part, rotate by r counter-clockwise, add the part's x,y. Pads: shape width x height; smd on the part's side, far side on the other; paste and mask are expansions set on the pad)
0402S [mil] "Based on C0402S footprint from PADS legacy"
  rect 15x24 smd: 1(-20,0) 2(20,0)
  body extent -22,-12 22,12, height 24
0603 [mm] "0603 from SM-752 data"
  rect 1x0.95 smd: 1(-0.8,0) 2(0.8,0)
  silkscreen extent -1.52,-0.69 1.52,0.69, body extent -0.87,-0.47 0.87,0.47, height 1
0603S [mil]
  rect 20x35 smd: 1(-30,0) 2(30,0)
  body extent -34,-19 34,19, height 39
0805_HV1 [mm] "Custom footprint based on analyzing multiple manufacturer recommendations"
  rrect10% 1x1.25 smd: 1(-1,0) 2(1,0)
  silkscreen extent -0.2,-0.75 0.2,0.75, body extent -1.1,-0.72 1.1,0.73, height 1.45
AssemblyNote [mil] "Assembly Note"
CONN_2510-6002 [mm] "3M 2500 series TS-0770-L December 15, 2011"
  rect 1.65x1.65 hole 1.016 mask+0: 1(-5.08,-1.27)
  round 1.65 hole 1.016 mask+0: 2(-5.08,1.27) 3(-2.54,-1.27) 4(-2.54,1.27) 5(0,-1.27) 6(0,1.27) 7(2.54,-1.27) 8(2.54,1.27) 9(5.08,-1.27) 10(5.08,1.27)
  silkscreen extent -10.01,-4.17 10.01,4.47, body extent -10.01,-4.11 10.01,4.52, height 9.92
FCC_disclaimer [mil]
Fiducial10-20 [mm]
  round 1 smd mask+0.5: 1(0,0)
  Top Layer keep-out circle w1.178: c0,0 r0.5
FP-A768KE276M1JLAE054_SMT_CAP_8MM3_8MM3-0 [mm]
  rrect5% 4.2x2.2 smd paste+0 mask+0: 1(-3.65,0) 2(3.65,0)
  silkscreen extent -6.42,-4.25 4.25,4.25, body extent -6,-4.5 6,4.5, height 0.25
FP-C3225X7R2A106K250AC_1210-MFG [mm]
  rrect9% 1.1x2.2 smd paste+0 mask+0: 1(-1.65,0) 2(1.65,0)
  silkscreen extent -0.72,-1.43 0.72,1.43, body extent -2.3,-1.53 2.3,1.53, height 0.25
FP-GCM188L81H104KA57D_0603-MFG [mm]
  rrect15% 0.65x0.7 smd paste+0 mask+0: 1(-0.675,0) 2(0.675,0)
  body extent -1.1,-0.55 1.1,0.55, height 0.25
FP-IQE022N06LM5CGSCATMA1_PG-WHTFN-9-MFG [mm]
  round 1.468 smd paste-1000 mask+0: 1-2-3-4(0.374,-0.395)
  round 0.36 smd paste-1000 mask+0: 5-6-7-8(-0.95,1.3)
  rrect22% 1.1x0.45 smd paste-1000 mask+0: 9(-1.35,0.395)
  Top Layer region: -0.475,0.45 1.205,0.45 1.205,-1.2 1.15,-1.2 1.15,-1.9 0.8,-1.9 0.8,-1.2 0.5,-1.2 0.5,-1.9 0.15,-1.9 0.15,-1.2 -0.15,-1.2 -0.15,-1.9 -0.5,-1.9 -0.5,-1.2 -0.8,-1.2 -0.8,-1.9 -1.15,-1.9 -1.15,-1.2 -1.205,-1.2 -1.205,-0.215 -0.475,-0.215
  Top Layer region: 1.15,1.1 -1.15,1.1 -1.15,1.9 -0.8,1.9 -0.8,1.45 -0.5,1.45 -0.5,1.9 -0.15,1.9 -0.15,1.45 0.15,1.45 0.15,1.9 0.5,1.9 0.5,1.45 0.8,1.45 0.8,1.9 1.15,1.9
  silkscreen extent -1.7,-2.58 1.7,1.7, body extent -1.65,-1.65 1.65,1.65, height 0.75
FP-ISZ034N06LM5ATMA1_TSDSON8-MFG [mm]
  round 0.81 smd paste-1000 mask-1000: 1-2-3(-0.325,-1.45)
  rrect29% 0.34x0.9 smd paste-1000 mask+0: 4(0.975,-1.45)
  round 2.061 smd paste-1000 mask-1000: 5-6-7-8(0,0.72)
  Top Layer region: -1.145,-0.46 1.145,-0.46 1.145,1.9 -1.145,1.9
  Top Layer region: -1.145,-1 0.495,-1 0.495,-1.9 -1.145,-1.9
  silkscreen extent -1.7,-2.58 1.7,1.7, body extent -1.8,-2 1.8,2, height 0.25
FP-KRL2012E-C-R010-F-T05_0508-MFG [mm]
  rrect14% 0.7x2.2 smd paste+0 mask+0: 1(-0.65,0) 2(0.65,0)
  silkscreen extent -0.72,-1.5 0.72,1.5, body extent -1.1,-1.2 1.1,1.2, height 0.25
FP-KRL2012E-M-R005-F-T5_0805_WIDE-MFG [mm]
  rrect14% 0.7x2.2 smd paste+0 mask+0: 1(-0.65,0) 2(0.65,0)
  silkscreen extent -0.72,-1.5 0.72,1.5, body extent -1.1,-1.2 1.1,1.2, height 0.25
FP-XGL1060-332MEC_SMT2_10MM0_11MM3-MFG [mm]
  rrect4% 2.38x8.5 smd paste+0 mask+0: 1(-3.325,0) 2(3.325,0)
  silkscreen extent -5.92,-5.9 5.25,5.9, body extent -5.35,-6 5.35,6, height 0.25
Harwin_M7582-05 [mil] "Single Operation 2.54mm Pitch Open Top Jumper Socket"
  body extent -98,-47 98,47, height 236
IEC_HotSurface_Small [mil]
  silkscreen extent -107,-93 107,92
Johnson_108-0740-001 [mm] "Banana Jack Uninsulated Standard Type"
  round 12 hole 6.858: 1(0,0)
  body extent -4.77,-5.43 4.75,5.57, height 2.39
Keystone5001 [mil] "For Keystone 500x miniature loop terminals"
  round 80 hole 40: 1(0,0)
  silkscreen extent -52,-52 52,52, body extent -49,-49 49,49, height 182
Keystone5004 [mil] "For Keystone 500x miniature loop terminals"
  round 80 hole 40: 1(0,0)
  silkscreen extent -52,-52 52,52, body extent -49,-49 49,49, height 182
Keystone5010 [mil] "Keystone Multipurpose loops"
  round 87 hole 63: 1(0,0)
  silkscreen extent -70,-70 70,70, body extent -63,-63 63,62, height 319
Keystone5011 [mil] "Keystone Multipurpose loops"
  round 87 hole 63: 1(0,0)
  silkscreen extent -70,-70 70,70, body extent -63,-63 63,62, height 319
Keystone5012 [mil] "Keystone Multipurpose loops"
  round 87 hole 63: 1(0,0)
  silkscreen extent -70,-70 70,70, body extent -63,-63 63,62, height 319
Keystone5013 [mil] "Keystone Multipurpose loops"
  round 87 hole 63: 1(0,0)
  silkscreen extent -70,-70 70,70, body extent -63,-63 63,62, height 319
Keystone5128 [mil] "Keystone Multipurpose loops"
  round 87 hole 63: 1(0,0)
  silkscreen extent -70,-70 70,70, body extent -63,-63 63,62, height 319
Keystone_1902C [mil] "Hex Standoff, 4-40 threaded, nylon"
  round 1 on Mech4: 0(0,0)
  body extent -145,-126 146,126, height 501
Net-Tie_10mil [mil] "10mil net tie, no solder mask opening, no solder paste"
  rect 10x10 smd paste-5 mask-5: 1(-10,0) 2(10,0)
  Top Layer region: -6,5 6,5 6,-5 -6,-5
Net-Tie_20milWide_60milLong [mil] "20mil net tie, no solder mask opening, no solder paste"
  rect 60x20 smd paste-10 mask-10: 1(-30,0) 2(30,0)
"NY PMS 440 0025 PH" [mm] "4-40 nylon screw and mounting hole"
  round 8 hole 3.2: 1(0,0)
  body extent -3.3,-3.3 3.3,3.3, height 2.69
PowerPAK_1212-8#1 [mm] "Vishay PowerPAK 1212-8, Body 3.4x3.2mm (max), Pitch 0.65mm, IPC Medium Density"
  rrect50% 0.73x0.4 smd paste-0.05 mask-0.05: 1(-1.535,0.991) 2(-1.535,0.33) 3(-1.535,-0.33) 4(-1.535,-0.991)
  rrect50% 0.71x0.4 smd paste-0.05 mask-0.05: 5(1.545,-0.991) 6(1.545,-0.33) 7(1.545,0.33) 8(1.545,0.991)
  rrect30% 0.33x0.6 on Top Paste: 9(-0.195,-1.55) 9(-0.195,1.55)
  rrect30% 0.33x3.7 on Top Solder: 9(-0.195,0)
  rrect11% 1.3x0.94 on Top Paste: 9(0.39,-0.57) 9(0.39,0.57)
  rrect6% 1.6x2.28 on Top Solder: 9(0.54,0)
  rrect9% 2.31x3.3 smd paste-2 mask-2: 9(0.745,0)
  Top Layer region: -0.41,-1.8 -0.41,1.8 -0.402,1.838 -0.381,1.871 -0.348,1.892 -0.31,1.9 -0.31,1.9 -0.08,1.9 -0.042,1.892 -0.009,1.871 0.012,1.838 0.02,1.8 0.02,1.8 0.02,-1.8 0.012,-1.838 -0.009,-1.871 -0.042,-1.892 -0.08,-1.9 -0.08,-1.9 -0.31,-1.9 -0.348,-1.892 -0.381,-1.871 -0.402,-1.838 -0.41,-1.8
  silkscreen extent -1.75,-1.75 1.75,1.75, body extent -1.65,-1.66 1.65,1.64, height 1.08
PowerPAK_1212-8#2 [mm] "Vishay PowerPAK 1212-8, Body 3.4x3.2mm (max), Pitch 0.65mm, IPC Medium Density"
  rrect50% 0.73x0.4 smd paste-0.05 mask-0.05: 1(-1.535,0.991) 2(-1.535,0.33) 3(-1.535,-0.33) 4(-1.535,-0.991)
  rrect50% 0.71x0.4 smd paste-0.05 mask-0.05: 5(1.545,-0.991) 6(1.545,-0.33) 7(1.545,0.33) 8(1.545,0.991)
  rrect30% 0.33x0.6 on Bottom Paste: 9(-0.195,-1.55) 9(-0.195,1.55)
  rrect30% 0.33x3.7 on Bottom Solder: 9(-0.195,0)
  rrect11% 1.3x0.94 on Bottom Paste: 9(0.39,-0.57) 9(0.39,0.57)
  rrect6% 1.6x2.28 on Bottom Solder: 9(0.54,0)
  rrect9% 2.31x3.3 smd paste-2 mask-2: 9(0.745,0)
  Top Layer region: -0.41,-1.8 -0.41,1.8 -0.402,1.838 -0.381,1.871 -0.348,1.892 -0.31,1.9 -0.31,1.9 -0.08,1.9 -0.042,1.892 -0.009,1.871 0.012,1.838 0.02,1.8 0.02,1.8 0.02,-1.8 0.012,-1.838 -0.009,-1.871 -0.042,-1.892 -0.08,-1.9 -0.08,-1.9 -0.31,-1.9 -0.348,-1.892 -0.381,-1.871 -0.402,-1.838 -0.41,-1.8
  silkscreen extent -1.75,-1.75 1.75,1.75, body extent -1.65,-1.66 1.65,1.64, height 1.08
RHA0040P-MFG [mm]
  rrect40% 0.6x0.25 smd paste+0 mask+0: 1(-2.9,2.25) 2(-2.9,1.75) 3(-2.9,1.25) 4(-2.9,0.75) 5(-2.9,0.25) 6(-2.9,-0.25) 7(-2.9,-0.75) 8(-2.9,-1.25) 9(-2.9,-1.75) 10(-2.9,-2.25) 21(2.9,-2.25) 22(2.9,-1.75) 23(2.9,-1.25) 24(2.9,-0.75) 25(2.9,-0.25) 26(2.9,0.25) 27(2.9,0.75) 28(2.9,1.25) 29(2.9,1.75) 30(2.9,2.25)
  rrect40% 0.25x0.6 smd paste+0 mask+0: 11(-2.25,-2.9) 12(-1.75,-2.9) 13(-1.25,-2.9) 14(-0.75,-2.9) 15(-0.25,-2.9) 16(0.25,-2.9) 17(0.75,-2.9) 18(1.25,-2.9) 19(1.75,-2.9) 20(2.25,-2.9) 31(2.25,2.9) 32(1.75,2.9) 33(1.25,2.9) 34(0.75,2.9) 35(0.25,2.9) 36(-0.25,2.9) 37(-0.75,2.9) 38(-1.25,2.9) 39(-1.75,2.9) 40(-2.25,2.9)
  rrect3% 3.3x3.3 smd paste-1000 mask+0: 41(0,0)
  silkscreen extent -3.87,-3.05 3.05,3.05, body extent -3.3,-3.3 3.3,3.3, height 0.25
Samtec_HTSW-103-07-x-D [mm] "Header, 2.54mm, 3x2, Gold, TH"
  rrect50% 1.55x1.55 hole 1.02: 1(-1.27,2.54)
  round 1.55 hole 1.02: 2(1.27,2.54) 3(-1.27,0) 4(1.27,0) 5(-1.27,-2.54) 6(1.27,-2.54)
  silkscreen extent -2.61,-3.91 2.61,4.3, body extent -2.51,-3.81 2.51,3.81, height 8.38
SMC [mil] "Molded Diode, 2-Leads, Body 6.9x5.8mm, IPC Medium Density, based on OnSemi component dimensions and land patterns"
  rect 110x150 smd: 1(-140.49,0) 2(140.49,0)
  silkscreen extent -221,-123 189,124, body extent -156,-116 156,116, height 91
SOD-123 [mm] "On Semi recommended land pattern"
  rect 0.915x1.22 smd: 1(-1.637,0) 2(1.637,0)
  silkscreen extent -2.74,-1.17 2.03,1.17, body extent -1.93,-0.9 1.93,0.9, height 1.35
SOD-323F [mm] "NXP recommended land pattern"
  rect 0.6x0.6 smd paste-0.05: 1(-1.1,0) 2(1.1,0)
  silkscreen extent -2.06,-0.86 1.53,0.86, body extent -1.35,-0.67 1.35,0.68, height 0.79
SW_218-8LP [mm] "SMD, 16-Leads, Body 11.33x5.8mm, Pitch 1.27mm"
  rect 1.27x0.76 smd: 1(-3.81,4.445) 2(-3.81,3.175) 3(-3.81,1.905) 4(-3.81,0.635) 5(-3.81,-0.635) 6(-3.81,-1.905) 7(-3.81,-3.175) 8(-3.81,-4.445) 9(3.81,-4.445) 10(3.81,-3.175) 11(3.81,-1.905) 12(3.81,-0.635) 13(3.81,0.635) 14(3.81,1.905) 15(3.81,3.175) 16(3.81,4.445)
  silkscreen extent -2.9,-5.67 2.9,5.9, body extent -4.22,-5.66 4.22,5.66, height 2.62
WEEE_Minimum [mil] "WEEElie bin"
  silkscreen extent -95,-172 99,104
WURTH_61300211121 [mm] "Header, 2.54mm, 2x1, TH"
  rrect50% 1.65x1.65 hole 1.15: 1(-1.27,0)
  round 1.65 hole 1.15: 2(1.27,0)
  body extent -2.54,-1.27 2.54,1.27, height 8.54
WURTH_61300311121 [mm] "Header, 2.54mm, 3x1, TH"
  rrect50% 1.65x1.65 hole 1.15: 1(-2.54,0)
  round 1.65 hole 1.15: 2(0,0) 3(2.54,0)
  body extent -3.81,-1.27 3.81,1.27, height 8.54
Wurth_61300511121 [mm] "Header, 2.54mm, 5x1, TH"
  rrect50% 1.65x1.65 hole 1.1: 1(-5.08,0)
  round 1.65 hole 1.1: 2(-2.54,0) 3(0,0) 4(2.54,0) 5(5.08,0)
  body extent -6.35,-1.27 6.35,1.27, height 8.54
WURTH_61300611121 [mm] "Header, 2.54mm, 6x1, TH"
  rrect50% 1.65x1.65 hole 1.15: 1(-6.35,0)
  round 1.65 hole 1.15: 2(-3.81,0) 3(-1.27,0) 4(1.27,0) 5(3.81,0) 6(6.35,0)
  body extent -7.62,-1.27 7.62,1.27, height 8.54

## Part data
C1 C7 C28 C32 C40: library part CMP-0086535-1, "0.1µF ±10% 50V Ceramic Capacitor X8L 0603 (1608 Metric)", Manufacturer="Murata Electronics North America", TempCo=-40+15%, Tolerance_%=10%
C2 C3 C4 C8 C9 C10 C11 C12 C14: library part CMP-0096021-1, "10 µF ±10% 100V Ceramic Capacitor X7R 1210 (3225 Metric)", Digikey Part Number=445-C3225X7R2A106K250ACCT-ND, Manufacturer=TDK, Mouser Part Number=810-C3225X7R2A106K25, Operating Temperature Range="-55°C to +125°C", TempCo=15%, Temperature Characteristic=X7R, Tolerance_%=10%, ValueDisplayed=10uF
C5 C6 C13 C15 C38 C41: library part CMP-0097690-1, "Cap Aluminum Polymer 27uF 63V 20% Solder Cylindrical 54m Ohm 1175mA 2000 hr 125°C T/R", Digikey Part Number=399-A768KE276M1JLAE054CT-ND, Leakage Current=340uA, Manufacturer=KEMET, Mouser Part Number=80-A768KE276M1JLAE54, Operating Temperature Range="-55°C to +125°C", Tolerance_%=20%, ValueDisplayed=27uF
C16: library part CMP-0007253-4, "CAP, CERM, 20 pF, 100 V, +/- 5%, C0G/NP0, 0603", Cap_Case=0603, Manufacturer=MuRata, Supplier Part Number 1=490-1334-1-ND, TempCo=C0G/NP0, Tolerance_%=5%, Value1=Unknown, Value2=100V, ValueDisplayed=20pF
C17 C39: library part CMP-0092433-2, "Multi-Layer Ceramic Capacitor 22uF 10V X5R ±20% 0603 Paper T/R", Manufacturer=Murata, Operating Temperature Range="-55°C to +85°C", TempCo=15%, Temperature Characteristic=X5R, Tolerance_%=20%, ValueDisplayed=22uF
C18: library part CMP-0084236-1, "CAP, CERM, 0.012 µF, 50 V,+/- 10%, X7R, AEC-Q200 Grade 1, 0603", Cap_Case=0603, Manufacturer=Kemet, TempCo=X7R, Tolerance_%=10%, Value2=50V, ValueDisplayed=0.012µF
C19: library part CMP-0006776-4, "CAP, CERM, 220 pF, 50 V, +/- 1%, C0G/NP0, 0603", Cap_Case=0603, Manufacturer=AVX, Supplier Part Number 1=478-3719-1-ND, TempCo=C0G/NP0, Tolerance_%=1%, Value1="0.083 ohm", Value2=50V, ValueDisplayed=220pF
C20: library part CMP-0086295-1, "CAP, CERM, 0.02 µF, 50 V,+/- 10%, X7R, 0603", Cap_Case=0603, Manufacturer=Yageo, TempCo=X7R, Tolerance_%=10%, Value2=50V, ValueDisplayed=0.02µF
C21: library part CMP-0750041-1, "CAP, CERM, 100 pF, 50 V,+/- 5%, C0G/NP0, AEC-Q200 Grade 1, 0603", Cap_Case=0603, Manufacturer=MuRata, TempCo=C0G/NP0, Tolerance_%=5%, Value2=50V, ValueDisplayed=100pF
C22 C23: library part CMP-0008176-2, "CAP, CERM, 680 pF, 100 V, +/- 5%, C0G/NP0, 0805", Cap_Case=0805, Manufacturer=MuRata, Supplier Part Number 1=490-1613-1-ND, TempCo=C0G/NP0, Tolerance_%=5%, Value1=Unknown, Value2=100V, ValueDisplayed=680pF
C24 C25: library part CMP-0006356-2, "CAP, CERM, 0.1 uF, 50 V, +/- 10%, X7R, AEC-Q200 Grade 1, 0402", Cap_Case=0402, Manufacturer=MuRata, Supplier Part Number 1=490-10672-1-ND, TempCo=X7R, Tolerance_%=10%, Value1=Unknown, Value2=50V, ValueDisplayed=0.1uF
C26 C27: library part CMP-0006618-2, "CAP, CERM, 0.1 uF, 100 V, +/- 10%, X5R, 0402", Cap_Case=0402, Manufacturer=MuRata, Supplier Part Number 1=490-10458-1-ND, TempCo=X5R, Tolerance_%=10%, Value1=Unknown, Value2=100V, ValueDisplayed=0.1uF
C29: library part CMP-0007099-4, "CAP, CERM, 0.1 uF, 100 V, +/- 10%, X7S, AEC-Q200 Grade 1, 0603", Cap_Case=0603, Manufacturer=TDK, Supplier Part Number 1=445-6938-1-ND, TempCo=X7S, Tolerance_%=10%, Value1="0.04959 ohm", Value2=100V, ValueDisplayed=0.1uF
C30: library part CMP-0860983-1, "CAP, CERM, 0.1 µF, 50 V,+/- 10%, X7R, 0402", Cap_Case=0402, Manufacturer="Passive Plus", TempCo=X7R, Tolerance_%=10%, Value2=50V, ValueDisplayed=0.1µF
C31: library part CMP-0064935-4, "CAP, CERM, 0.1 uF, 100 V,+/- 10%, X7R, AEC-Q200 Grade 1, 0603", Cap_Case=0603, Manufacturer=MuRata, Supplier Part Number 1=490-13420-1-ND, TempCo=X7R, Tolerance_%=10%, Value1=Unknown, Value2=100V, ValueDisplayed=0.1uF
C33: library part CMP-0006762-4, "CAP, CERM, 100 pF, 50 V, +/- 1%, C0G/NP0, 0603", Cap_Case=0603, Manufacturer=AVX, Supplier Part Number 1=478-6202-1-ND, TempCo=C0G/NP0, Tolerance_%=1%, Value1=Unknown, Value2=50V, ValueDisplayed=100pF
C34 C35 C36: library part CMP-0006723-4, "CAP, CERM, 1000 pF, 100 V, +/- 5%, X7R, 0603", Cap_Case=0603, Manufacturer=AVX, Supplier Part Number 1=478-3698-1-ND, TempCo=X7R, Tolerance_%=5%, Value1="0.276 ohm", Value2=100V, ValueDisplayed=1000pF
C37: library part CMP-0007185-4, "CAP, CERM, 150 pF, 50 V, +/- 5%, C0G/NP0, 0603", Cap_Case=0603, Manufacturer=MuRata, Supplier Part Number 1=490-1431-1-ND, TempCo=C0G/NP0, Tolerance_%=5%, Value1=Unknown, Value2=50V, ValueDisplayed=150pF
C42: library part CMP-0006792-4, "CAP, CERM, 56 pF, 50 V, +/- 1%, C0G/NP0, 0603", Cap_Case=0603, Manufacturer=AVX, Supplier Part Number 1=478-7922-1-ND, TempCo=C0G/NP0, Tolerance_%=1%, Value1=Unknown, Value2=50V, ValueDisplayed=56pF
D1 D2: library part CMP-0028433-2, "Diode, Schottky, 60 V, 5 A, SMC", Manufacturer="Diodes Inc.", Value1=5A, Value2=0.7V
D3 D4: library part CMP-0077011-2, "Diode, Schottky, 60 V, 1 A, SOD-323F", Manufacturer=Nexperia, Value1=1A, Value2=0.66V
D5 D6: library part CMP-0005740-3, "Diode, Zener, 10 V, 500 mW, SOD-123", Manufacturer="ON Semiconductor", Power_W=500mW, Value1=0.5W
FID1 FID2 FID3 FID4 FID5 FID6: library part CMP-0077181-1, "Fiducial mark.  There is nothing to buy or mount.", Manufacturer=N/A
H1 H2 H3 H4: library part CMP-0003617-1, "Machine Screw, Round, #4-40 x 1/4, Nylon, Philips panhead", Manufacturer="B&F Fastener Supply", Supplier Part Number 1=H542-ND
H5 H6 H7 H8: library part CMP-0003610-1, "Standoff, Hex, 0.5\"L #4-40 Nylon", Manufacturer=Keystone, Supplier Part Number 1=36-1902C-ND
J1 J2 J3 J4: library part CMP-0055387-2, "Standard Banana Jack, Uninsulated, 15A", Manufacturer="Cinch Connectivity", Supplier Part Number 1=J147-ND
J5 J6: library part CMP-0054801-2, "Header, 2.54 mm, 6x1, Gold, TH", Color=Black, Manufacturer="Wurth Elektronik", Supplier Part Number 1=732-5319-ND
J7 J8 J9 J10 J11 J13 J14 JP8 JP10 JP11 JP12: library part CMP-0054794-2, "Header, 2.54 mm, 2x1, Gold, TH", Color=Black, Manufacturer="Wurth Elektronik", Supplier Part Number 1=732-5315-ND
J12: library part CMP-0055448-2, "Header (shrouded), 100mil, 5x2, High-Temperature, Gold, TH", Manufacturer=3M, Supplier Part Number 1=MHC10K-ND
JP1 JP2 JP3 JP5 JP7 JP9: library part CMP-0054796-4, "Header, 2.54 mm, 3x1, Gold, TH", Manufacturer="Wurth Elektronik", Supplier Part Number 1=732-5316-ND
JP4: library part CMP-0055587-2, "Header, 2.54mm, 3x2, Gold, TH", Color=Natural, Manufacturer=Samtec, Supplier Part Number 1=HTSW-103-07-G-D-ND
JP6: library part CMP-0084909-1, "Header, 2.54mm, 5x1, Gold, TH", Color=Black, Current_A=3A, Manufacturer="Wurth Elektronik", Voltage_V=250V
L1: library part CMP-0097455-1, "Shielded Power Inductors 3.3uH 22A 5.7mOhm", Manufacturer=Coilcraft, Operating Temperature Range=to, Self Resonant Frequency=21MHz, Test Frequency=1MHz, Tolerance_%=20%
Logo3: library part CMP-0074847-1, "FCC_disclaimer"
Logo4: library part CMP-0074769-3, Manufacturer="Texas Instruments"
Logo5 Logo6: library part CMP-0074837-2, "IEC 61010-1 Hot Surface Warning", Manufacturer="Texas Instruments"
NT1 NT2: library part CMP-0078142-6, "Single point connection between nets.", Manufacturer=N/A
Q1 Q1A Q2 Q3 Q3A Q4: library part CMP-0097450-1, "N-Channel 60 V 19A (Ta), 112A (Tc) 2.5W (Ta), 83W (Tc) Surface Mount PG-TSDSON-8-26", Digikey Part Number=448-ISZ034N06LM5ATMA1CT-ND, Drain To Source Breakdown Voltage=60V, Input Capacitace At Vds="2600pF @ 30V", Manufacturer=Infineon, Mouser Part Number=726-ISZ034N06LM5ATMA, Operating Temperature Range="-55°C to +175°C", Power_W=83W, Pulse Drain Current=448A, Typ Forward Diode Voltage=0.81V
Q3B Q3C: library part CMP-0121112-1, "MOSFET N-Channel 60 V 24A (Ta), 151A (Tc) 2.5W (Ta), 100W (Tc) Surface Mount PG-WHTFN-9", Digikey Part Number=448-IQE022N06LM5CGSCATMA1CT-ND, Drain To Source Breakdown Voltage=60V, Input Capacitace At Vds="3400pF @ 30V", Manufacturer=Infineon, Mouser Part Number=726-IQE022N06LM5CGSC, Operating Temperature Range="-55°C to +175°C", Power_W=2.5W, Pulse Drain Current=604A, Typ Forward Diode Voltage=0.79V
Q5 Q6: library part CMP-0000115-4, "MOSFET, P-CH, -60 V, -3.6 A, PowerPAK 1212", Alternate Manufacturer=None, Manufacturer=Vishay-Siliconix, Value1=0.1, Value2="15 nC"
R1 R44: library part CMP-0023292-5, "RES, 82.0 k, 1%, 0.1 W, 0603", Manufacturer=Yageo, Power_W=100mW, Supplier Part Number 1=311-82.0KHRCT-ND, TempCo="100 ppm/C", Tolerance_%=1%, Value2=0.1W, Value_Code=82k0, ValueDisplayed=82.0k
R2 R18: library part CMP-0023148-5, "RES, 4.30 k, 1%, 0.1 W, 0603", Manufacturer=Yageo, Power_W=100mW, Supplier Part Number 1=311-4.30KHRCT-ND, TempCo="100 ppm/C", Tolerance_%=1%, Value2=0.1W, Value_Code=4k30, ValueDisplayed=4.30k
R3 R4: library part CMP-0090651-1, "5 mOhms ±1% 1W Chip Resistor Wide 0805 (2012 Metric), 0508 Automotive AEC-Q200, Current Sense Metal Foil", Digikey Part Number=408-1595-1-ND, Manufacturer=Susumu, Mouser Part Number=754-KRL2012EMR005FT5, Operating Temperature Range="-55°C to +155°C", Power_W=1W, TempCo=50ppm/°C, Tolerance_%=1%
R5 R56: library part CMP-0025725-4, "RES, 180 k, 5%, 0.1 W, AEC-Q200 Grade 0, 0603", Manufacturer=Vishay-Dale, Power_W=100mW, Supplier Part Number 1=541-180KGCT-ND, TempCo="200 ppm/C", Tolerance_%=5%, Value2=0.1W, Value_Code=180k
R6: library part CMP-0097451-1, "10 mOhms ±1% 1W Chip Resistor Wide 0805 (2012 Metric), 0508 Automotive AEC-Q200, Current Sense Metal Foil", Manufacturer=Susumu, Operating Temperature Range="-55°C to +155°C", Power_W=1W, TempCo=50ppm/°C, Tolerance_%=1%
R7 R8 R9 R10 R13 R39 R58 R59: library part CMP-0025804-4, "RES, 3.0, 5%, 0.1 W, AEC-Q200 Grade 0, 0603", Manufacturer=Vishay-Dale, Power_W=100mW, Supplier Part Number 1=541-3.0GCT-ND, TempCo="200 ppm/C", Tolerance_%=5%, Value2=0.1W, Value_Code=3R00, ValueDisplayed=3.0
R11 R12: library part CMP-0022004-4, "RES, 10.0, 1%, 0.25 W, AEC-Q200 Grade 0, 0603", Manufacturer=Vishay-Dale, Power_W=250mW, Supplier Part Number 1=541-10.0SCT-ND, TempCo="100 ppm/C", Tolerance_%=1%, Value2=0.25W, Value_Code=10R0, ValueDisplayed=10.0
R14: library part CMP-0023267-5, "RES, 75.0 k, 1%, 0.1 W, 0603", Manufacturer=Yageo, Power_W=100mW, Supplier Part Number 1=311-75.0KHRCT-ND, TempCo="100 ppm/C", Tolerance_%=1%, Value2=0.1W, Value_Code=75k0, ValueDisplayed=75.0k
R15: library part CMP-0022778-5, "RES, 12.7 k, 1%, 0.1 W, 0603", Manufacturer=Yageo, Power_W=100mW, Supplier Part Number 1=311-12.7KHRCT-ND, TempCo="100 ppm/C", Tolerance_%=1%, Value2=0.1W, Value_Code=12k7, ValueDisplayed=12.7k
R16: library part CMP-0023653-3, "RES, 10.0 k, 0.1%, 0.1 W, 0603", Manufacturer="Yageo America", Power_W=100mW, TempCo="25 ppm/C", Tolerance_%=0.1%, Value2=0.1W, Value_Code=10k0, ValueDisplayed=10.0k
R17 R40 R41 R42 R43 R46 R47 R48 R49 R50 R57: library part CMP-0023343-3, "RES, 0, 1%, 0.1 W, AEC-Q200 Grade 0, 0603", Manufacturer="Stackpole Electronics Inc", Power_W=100mW, Supplier Part Number 1=RMCF0603ZT0R00CT-ND, TempCo=ppm/C, Tolerance_%=1%, Value2=0.1W, Value_Code=0
R19: library part CMP-0022599-4, "RES, 7.15 k, 1%, 0.1 W, AEC-Q200 Grade 0, 0603", Manufacturer=Vishay-Dale, Power_W=100mW, Supplier Part Number 1=541-7.15KHCT-ND, TempCo="100 ppm/C", Tolerance_%=1%, Value2=0.1W, Value_Code=7k15, ValueDisplayed=7.15k
R20 R29: library part CMP-0023198-5, "RES, 5.10 k, 1%, 0.1 W, 0603", Manufacturer=Yageo, Power_W=100mW, Supplier Part Number 1=311-5.10KHRCT-ND, TempCo="100 ppm/C", Tolerance_%=1%, Value2=0.1W, Value_Code=5k10, ValueDisplayed=5.10k
R21: library part CMP-0023167-5, "RES, 51.0 k, 1%, 0.1 W, 0603", Manufacturer=Yageo, Power_W=100mW, Supplier Part Number 1=311-51.0KHRCT-ND, TempCo="100 ppm/C", Tolerance_%=1%, Value2=0.1W, Value_Code=51k0, ValueDisplayed=51.0k
R22 R23: library part CMP-0023000-5, "RES, 2.00 k, 1%, 0.1 W, 0603", Manufacturer=Yageo, Power_W=100mW, Supplier Part Number 1=311-2.00KHRCT-ND, TempCo="100 ppm/C", Tolerance_%=1%, Value2=0.1W, Value_Code=2k00, ValueDisplayed=2.00k
R24: library part CMP-0022481-5, "RES, 511, 1%, 0.1 W, AEC-Q200 Grade 0, 0603", Manufacturer=Vishay-Dale, Power_W=100mW, Supplier Part Number 1=541-511HCT-ND, TempCo="100 ppm/C", Tolerance_%=1%, Value2=0.1W, Value_Code=511R, ValueDisplayed=511
R25: library part CMP-0022115-4, "RES, 1.15 k, 1%, 0.1 W, AEC-Q200 Grade 0, 0603", Manufacturer=Vishay-Dale, Power_W=100mW, Supplier Part Number 1=541-1.15KHCT-ND, TempCo="100 ppm/C", Tolerance_%=1%, Value2=0.1W, Value_Code=1k15, ValueDisplayed=1.15k
R26: library part CMP-0022891-5, "RES, 1.87 k, 1%, 0.1 W, 0603", Manufacturer=Yageo, Power_W=100mW, Supplier Part Number 1=311-1.87KHRCT-ND, TempCo="100 ppm/C", Tolerance_%=1%, Value2=0.1W, Value_Code=1k87, ValueDisplayed=1.87k
R27: library part CMP-0022996-5, "RES, 2.70 k, 1%, 0.1 W, 0603", Manufacturer=Yageo, Power_W=100mW, Supplier Part Number 1=311-2.70KHRCT-ND, TempCo="100 ppm/C", Tolerance_%=1%, Value2=0.1W, Value_Code=2k70, ValueDisplayed=2.70k
R28: library part CMP-0022381-4, "RES, 3.83 k, 1%, 0.1 W, AEC-Q200 Grade 0, 0603", Manufacturer=Vishay-Dale, Power_W=100mW, Supplier Part Number 1=541-3.83KHCT-ND, TempCo="100 ppm/C", Tolerance_%=1%, Value2=0.1W, Value_Code=3k83, ValueDisplayed=3.83k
